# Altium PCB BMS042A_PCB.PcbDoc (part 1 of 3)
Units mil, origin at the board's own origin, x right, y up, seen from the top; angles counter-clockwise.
Board outline 4409.45 x 3307 mil, 6 copper layers (Top Layer, Layer 2 - PGND, Layer 3, Layer 4, Layer 5 - PGND, Bottom Layer), stack 60.8 mil thick; 273 components, 77 nets, 544 pads, 927 vias.
Unrouted connection lines stored in the file: 219.
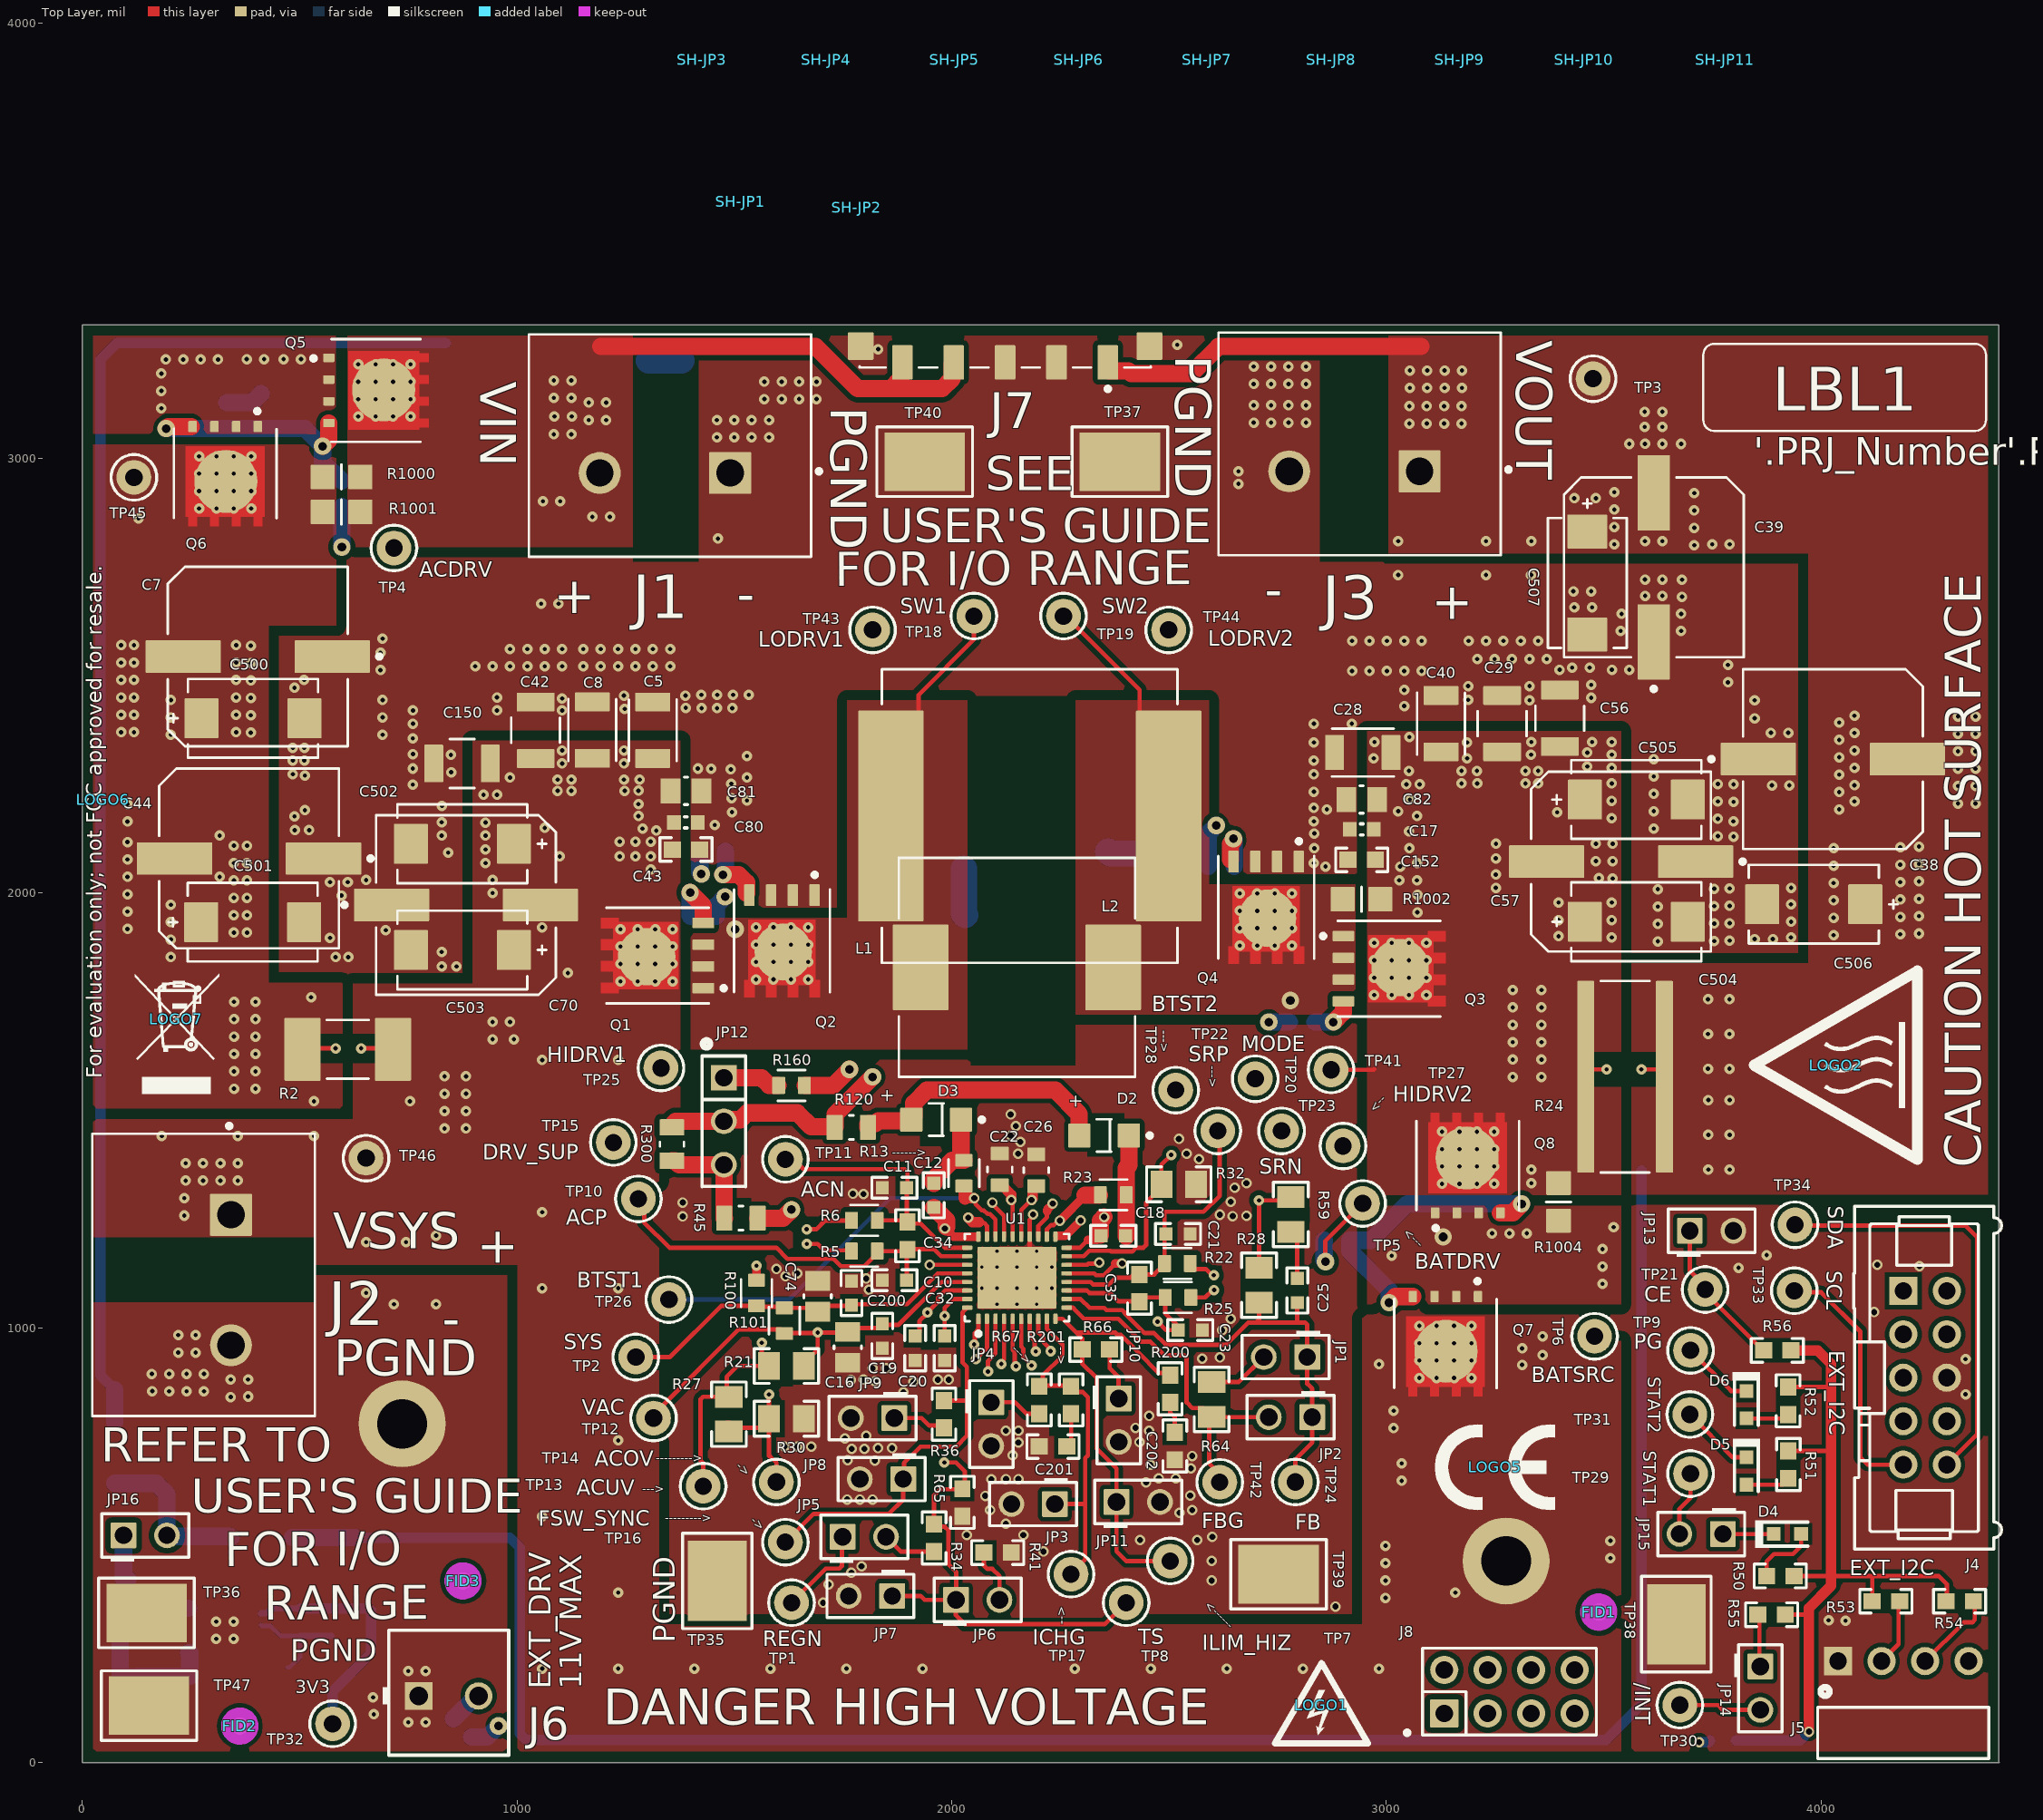
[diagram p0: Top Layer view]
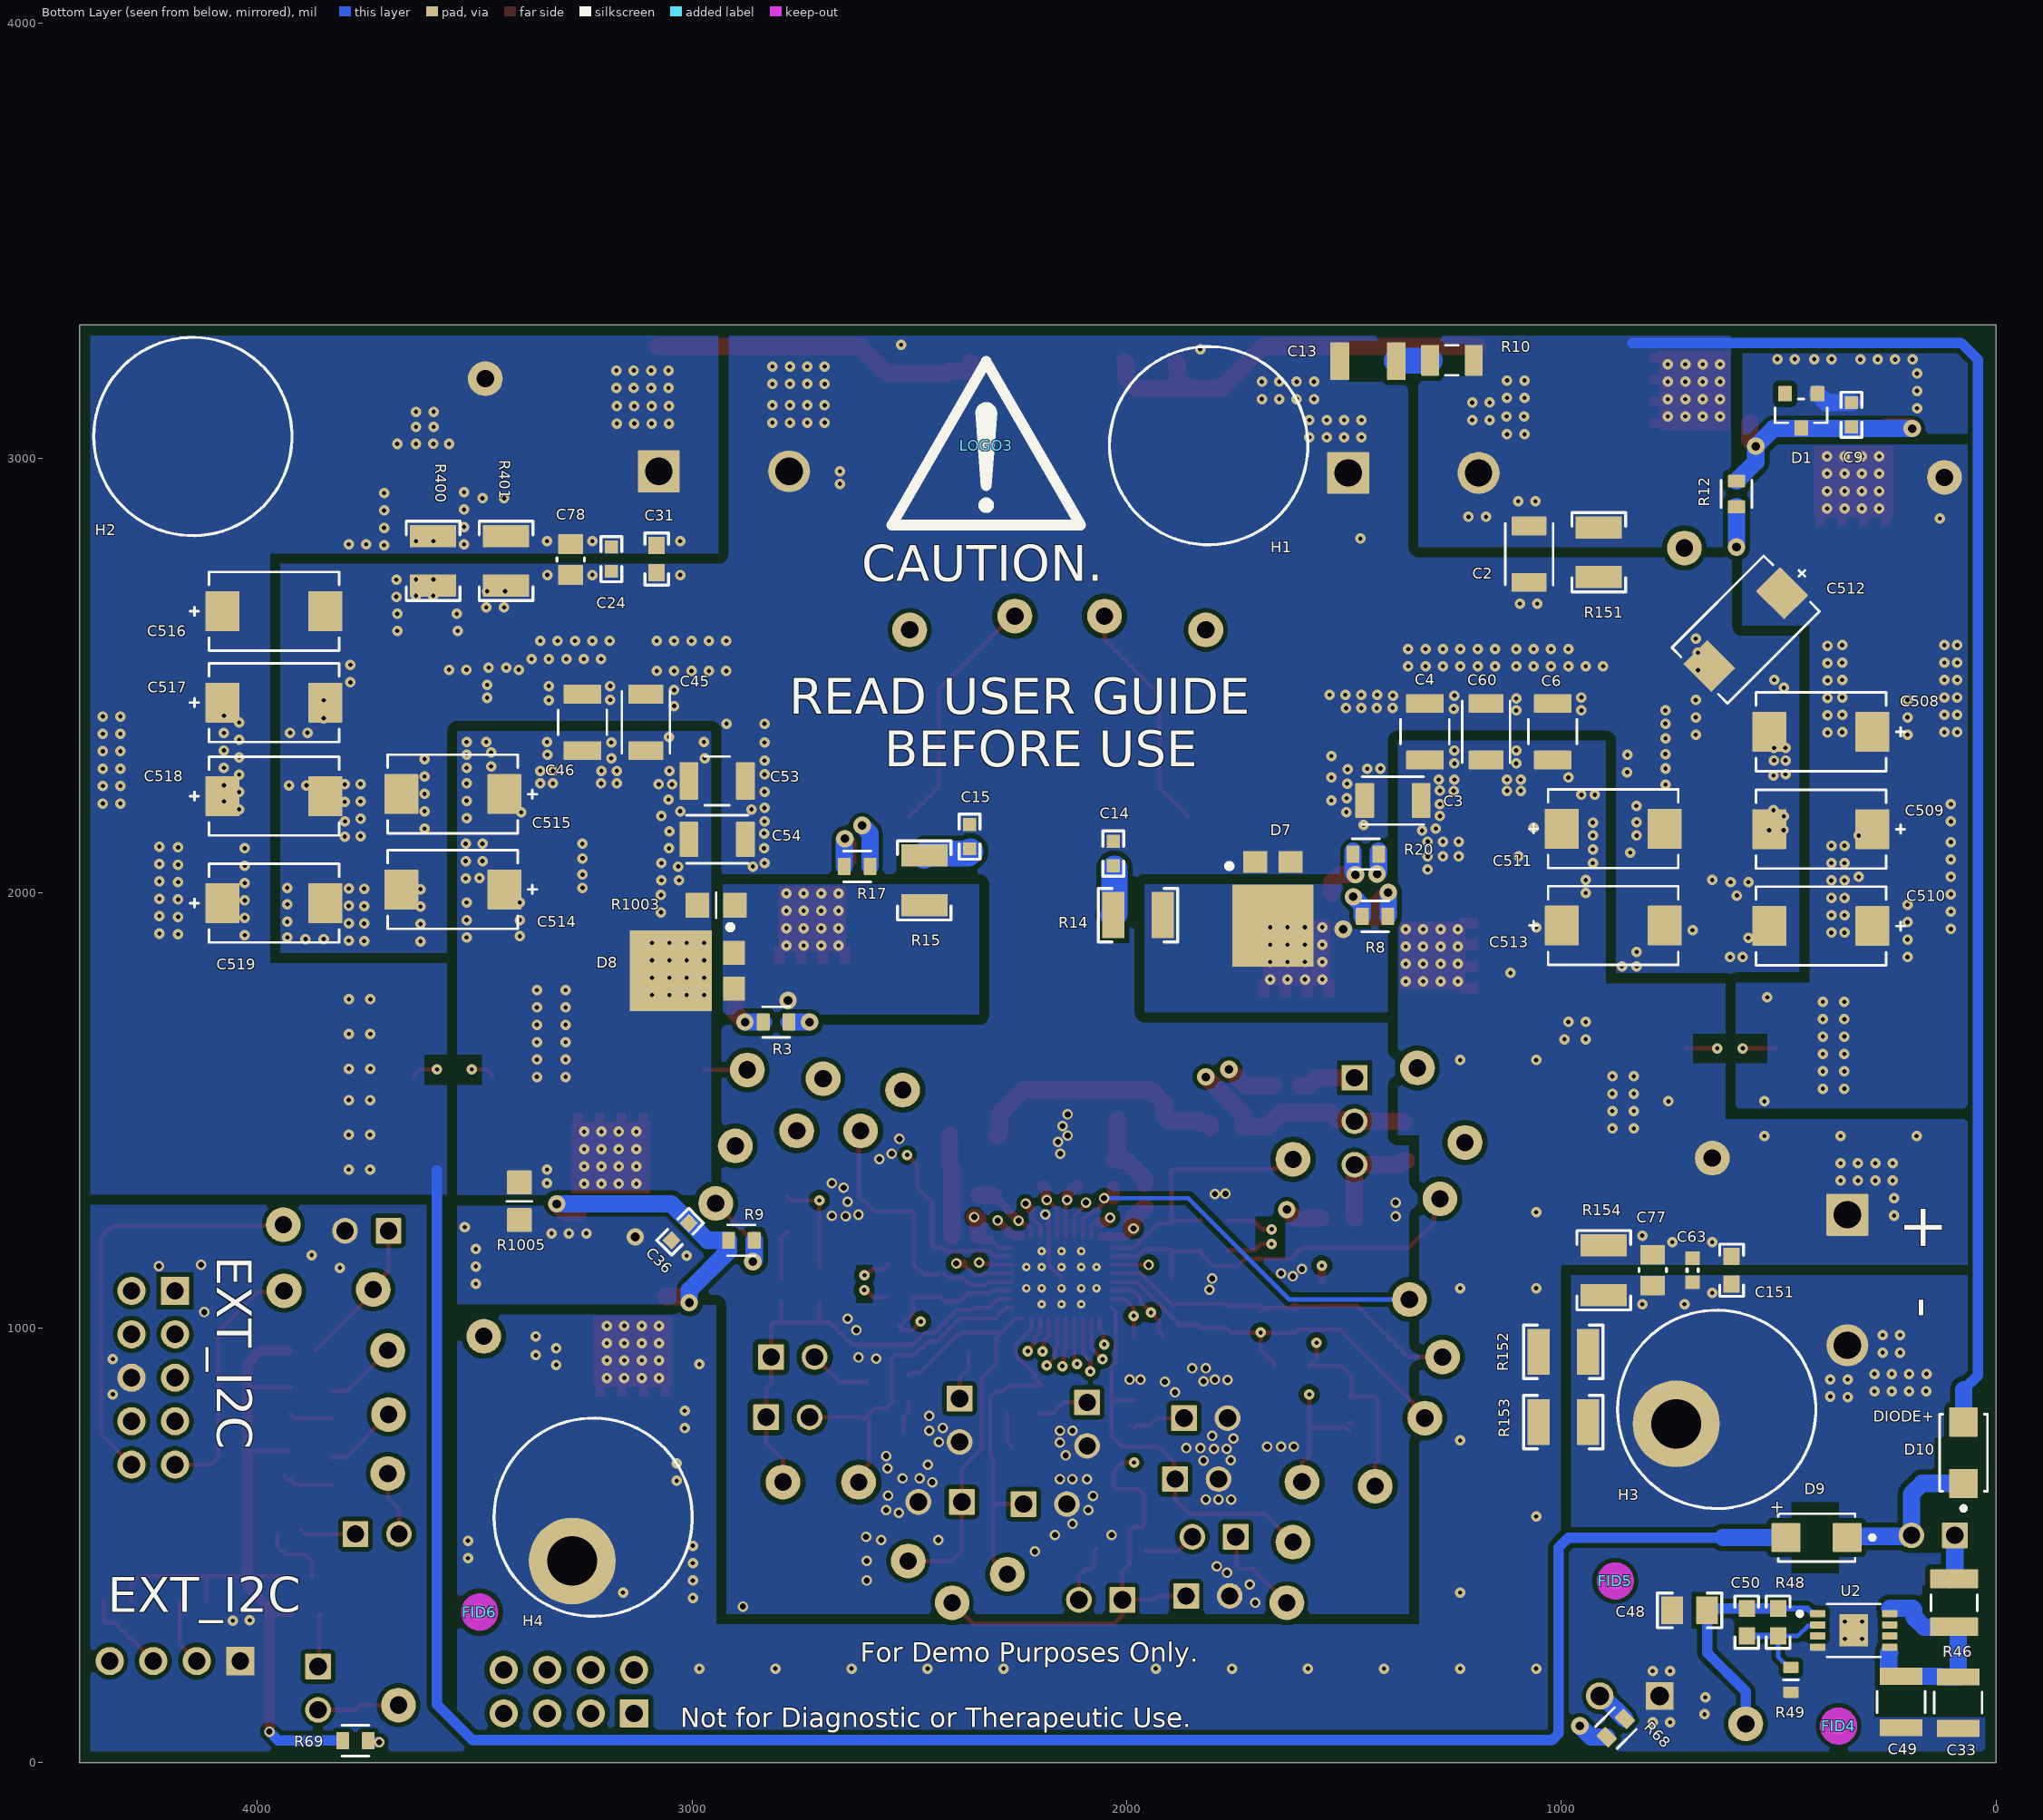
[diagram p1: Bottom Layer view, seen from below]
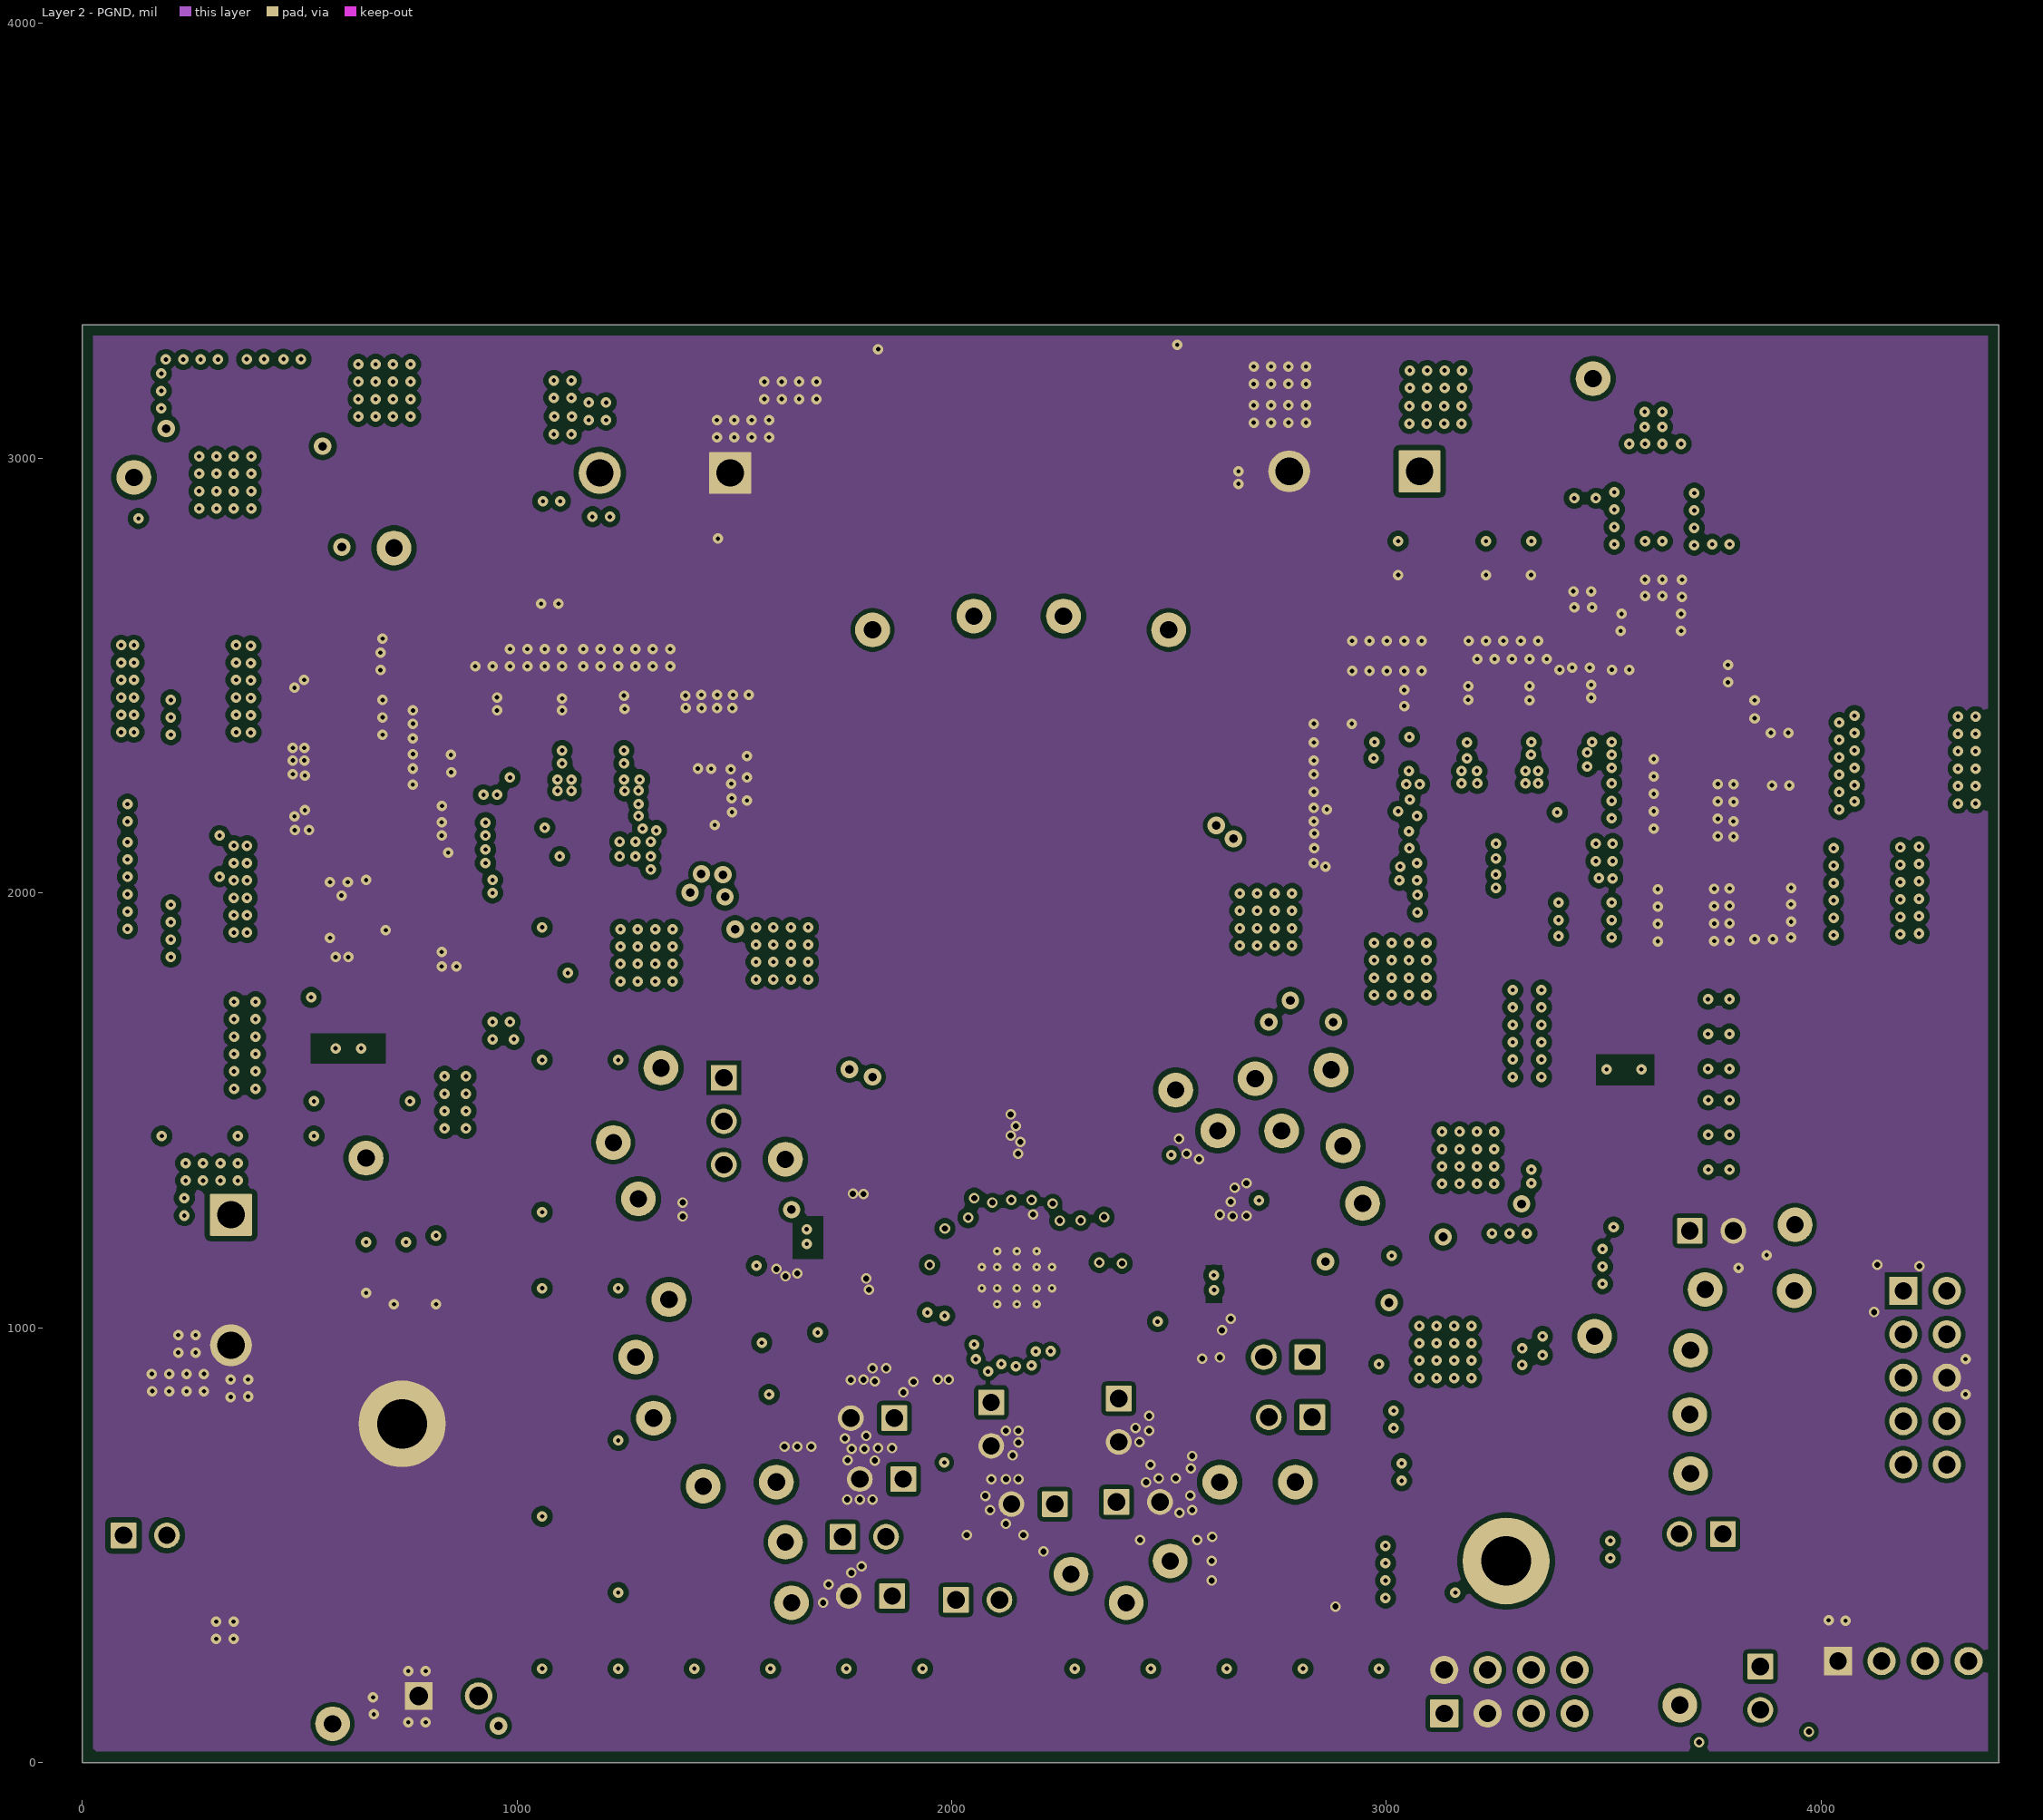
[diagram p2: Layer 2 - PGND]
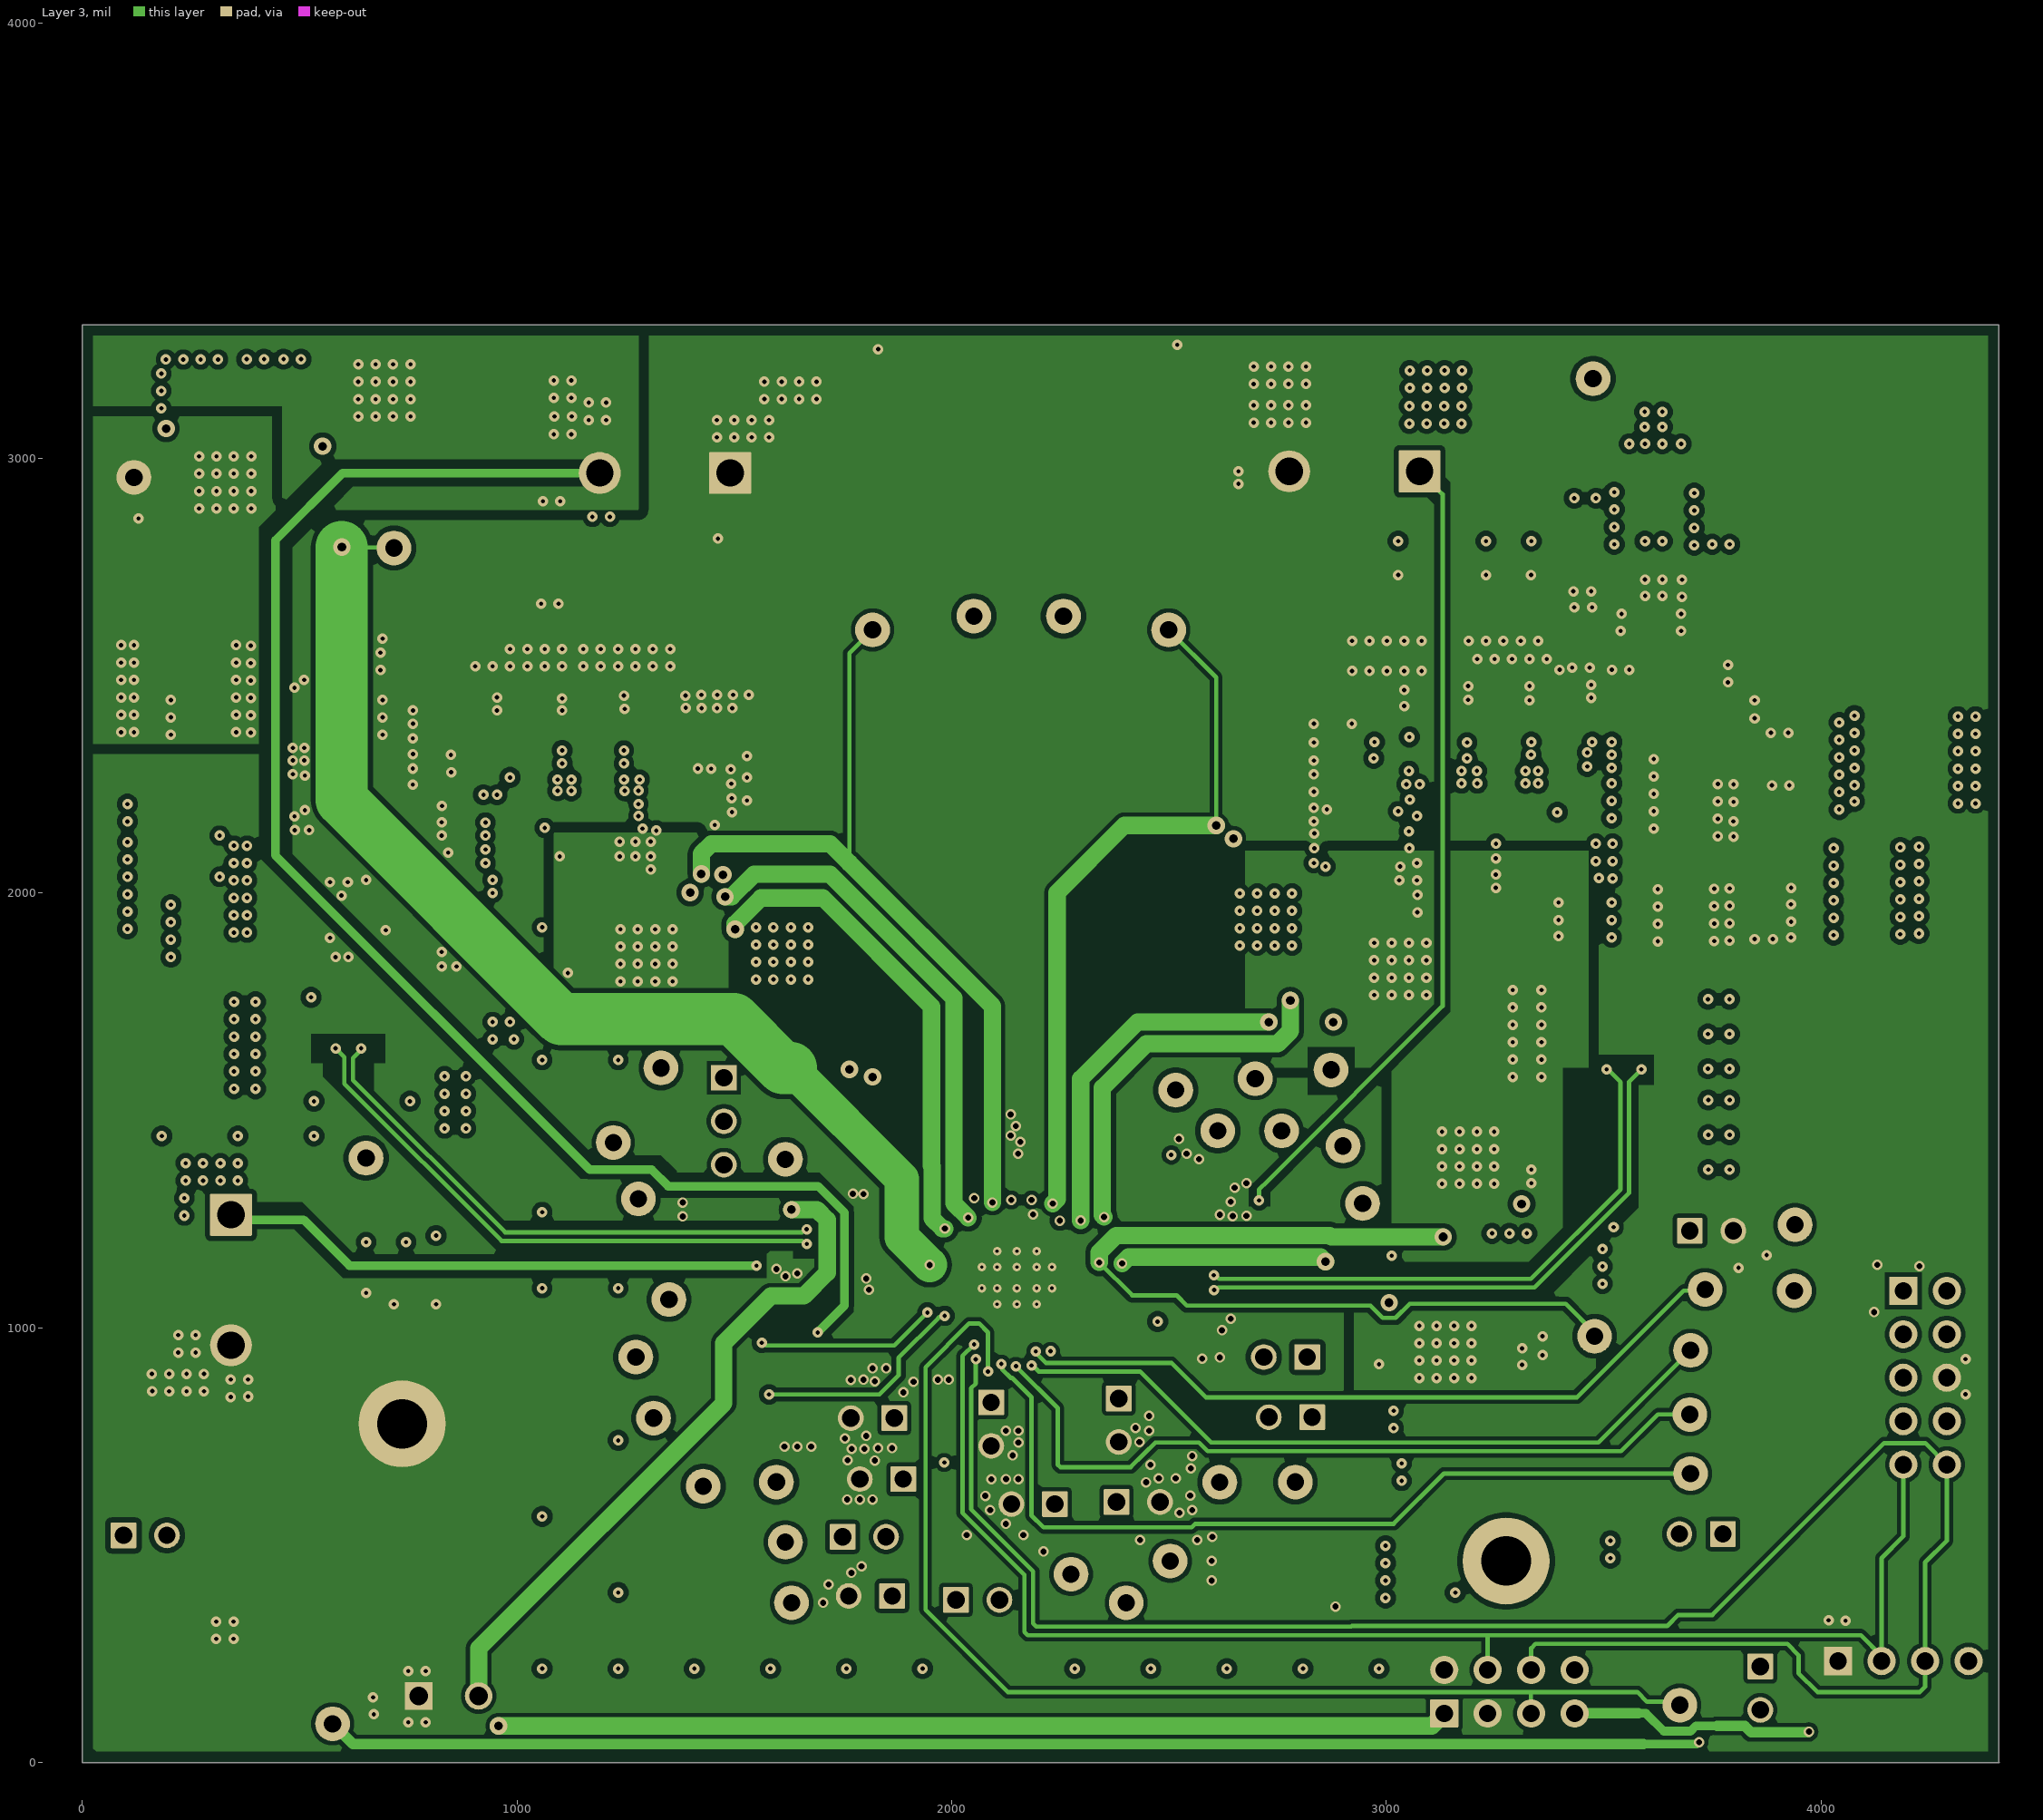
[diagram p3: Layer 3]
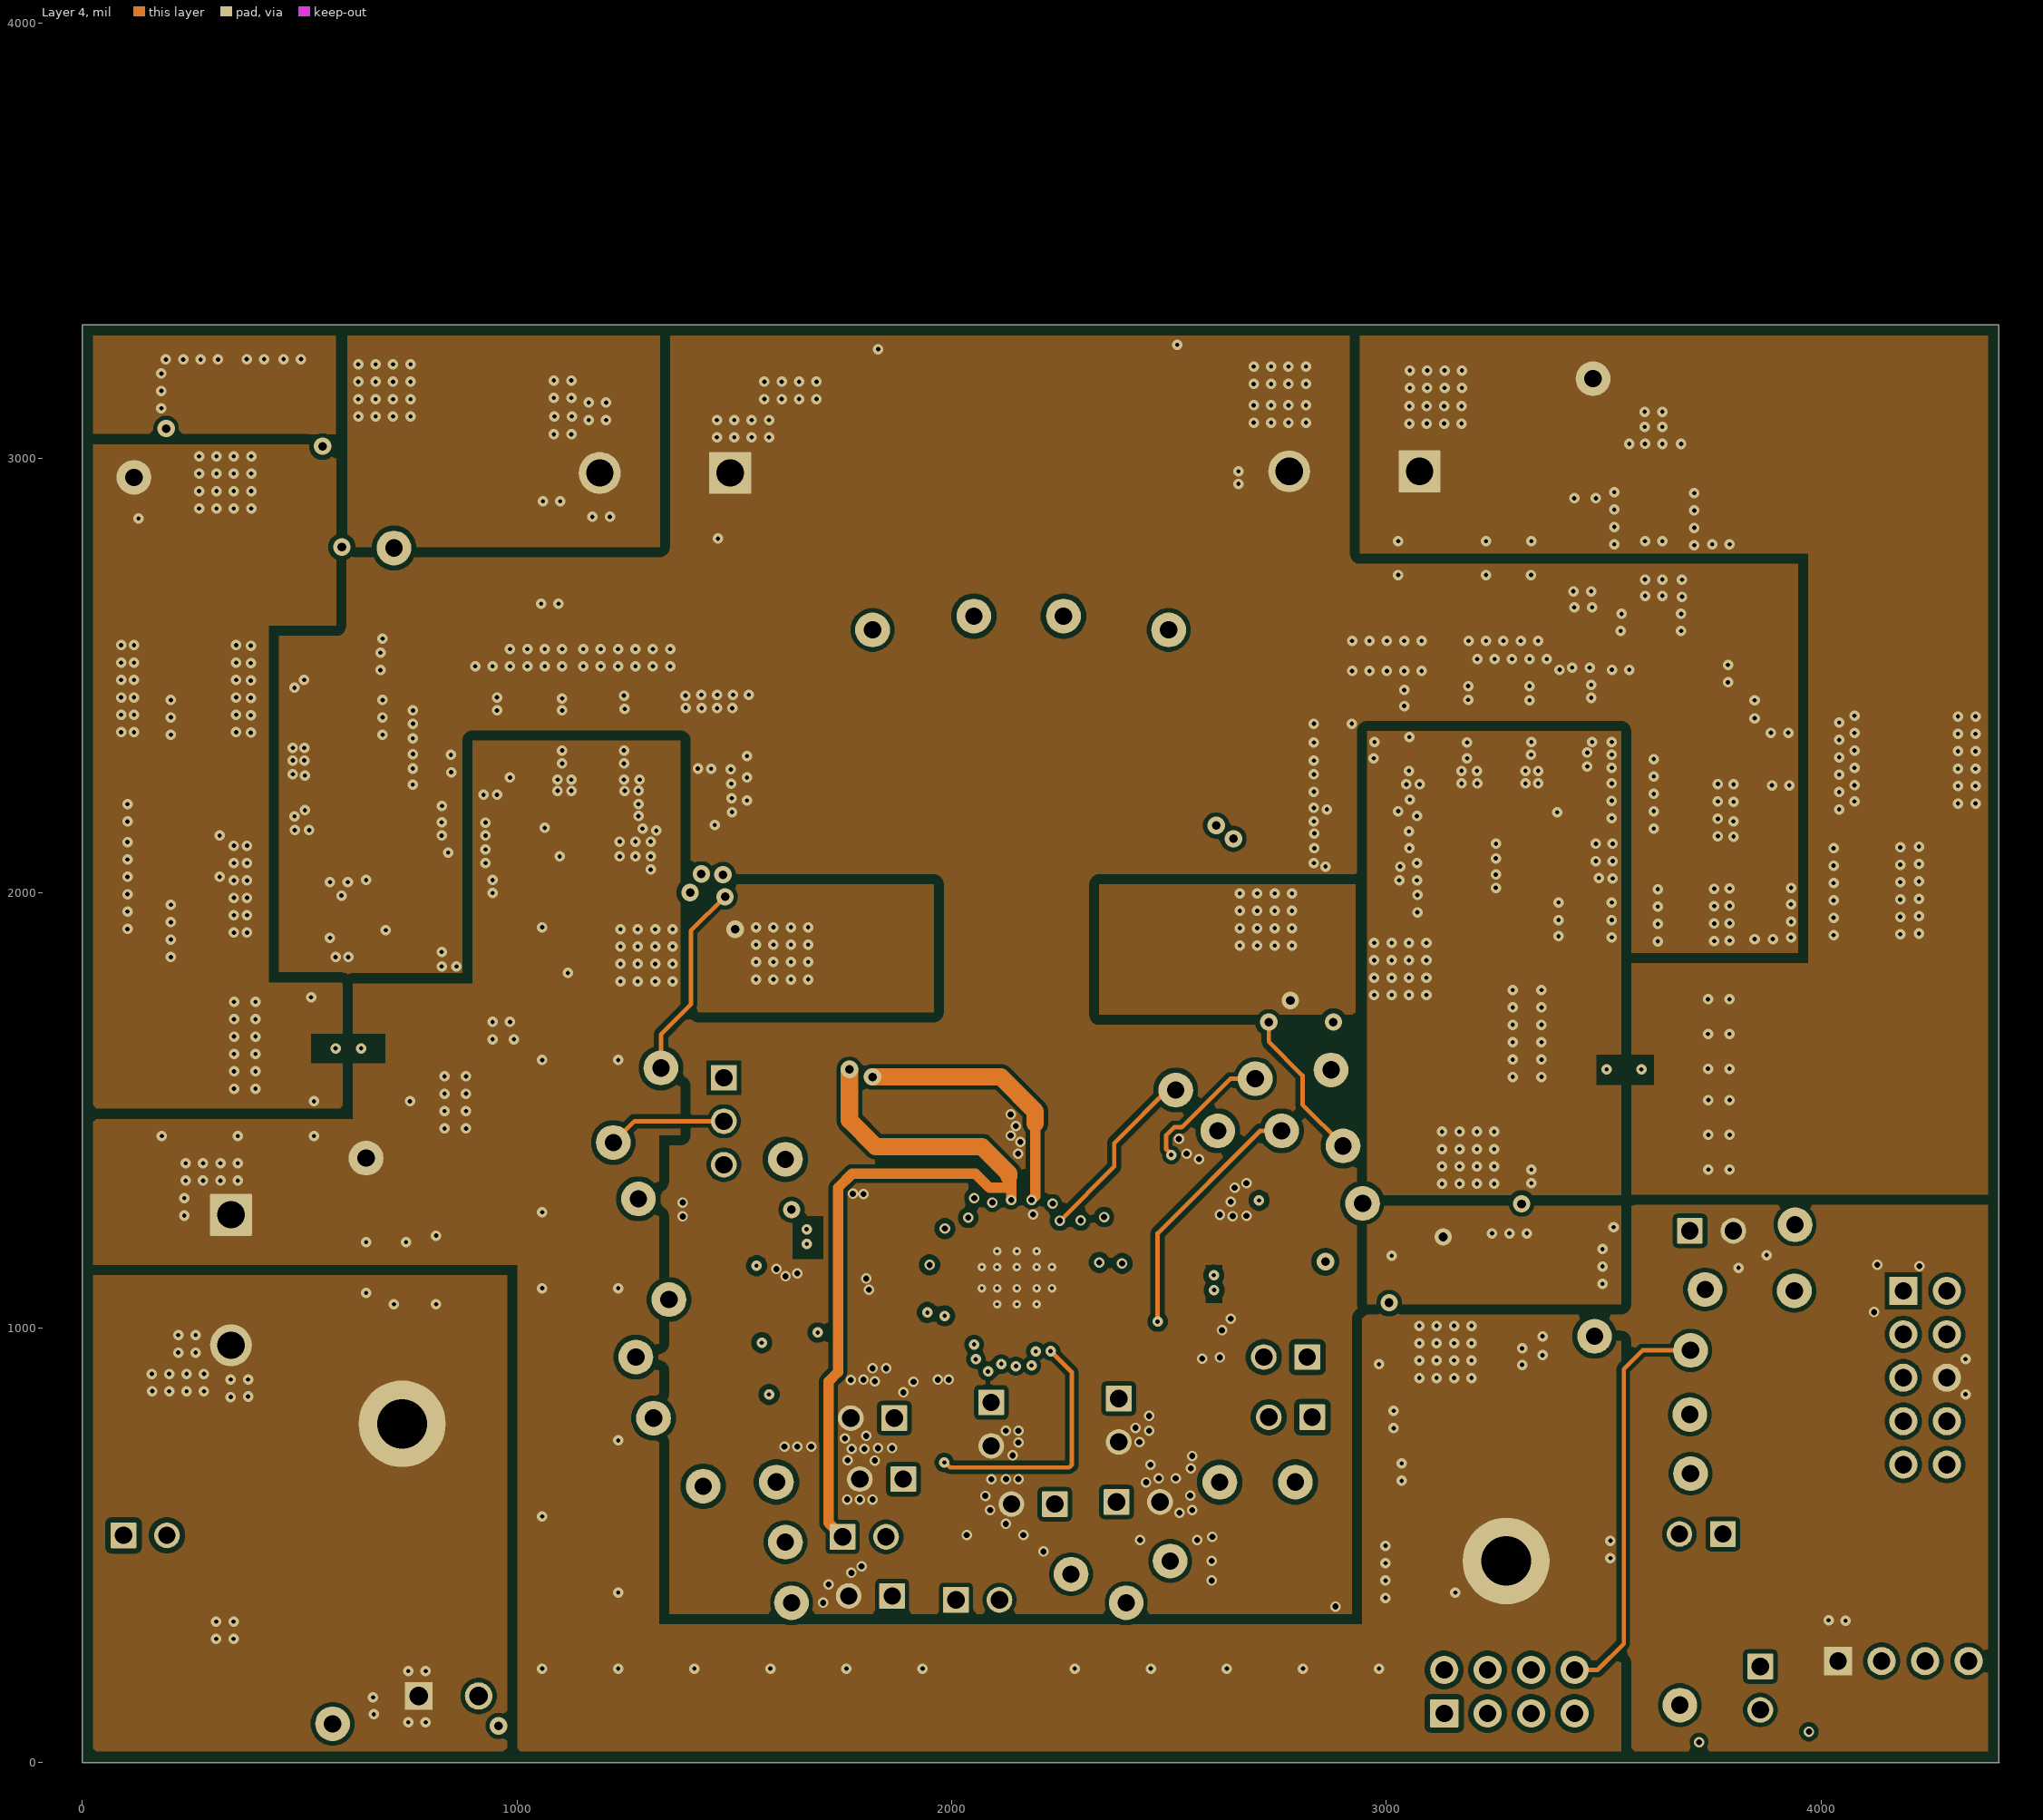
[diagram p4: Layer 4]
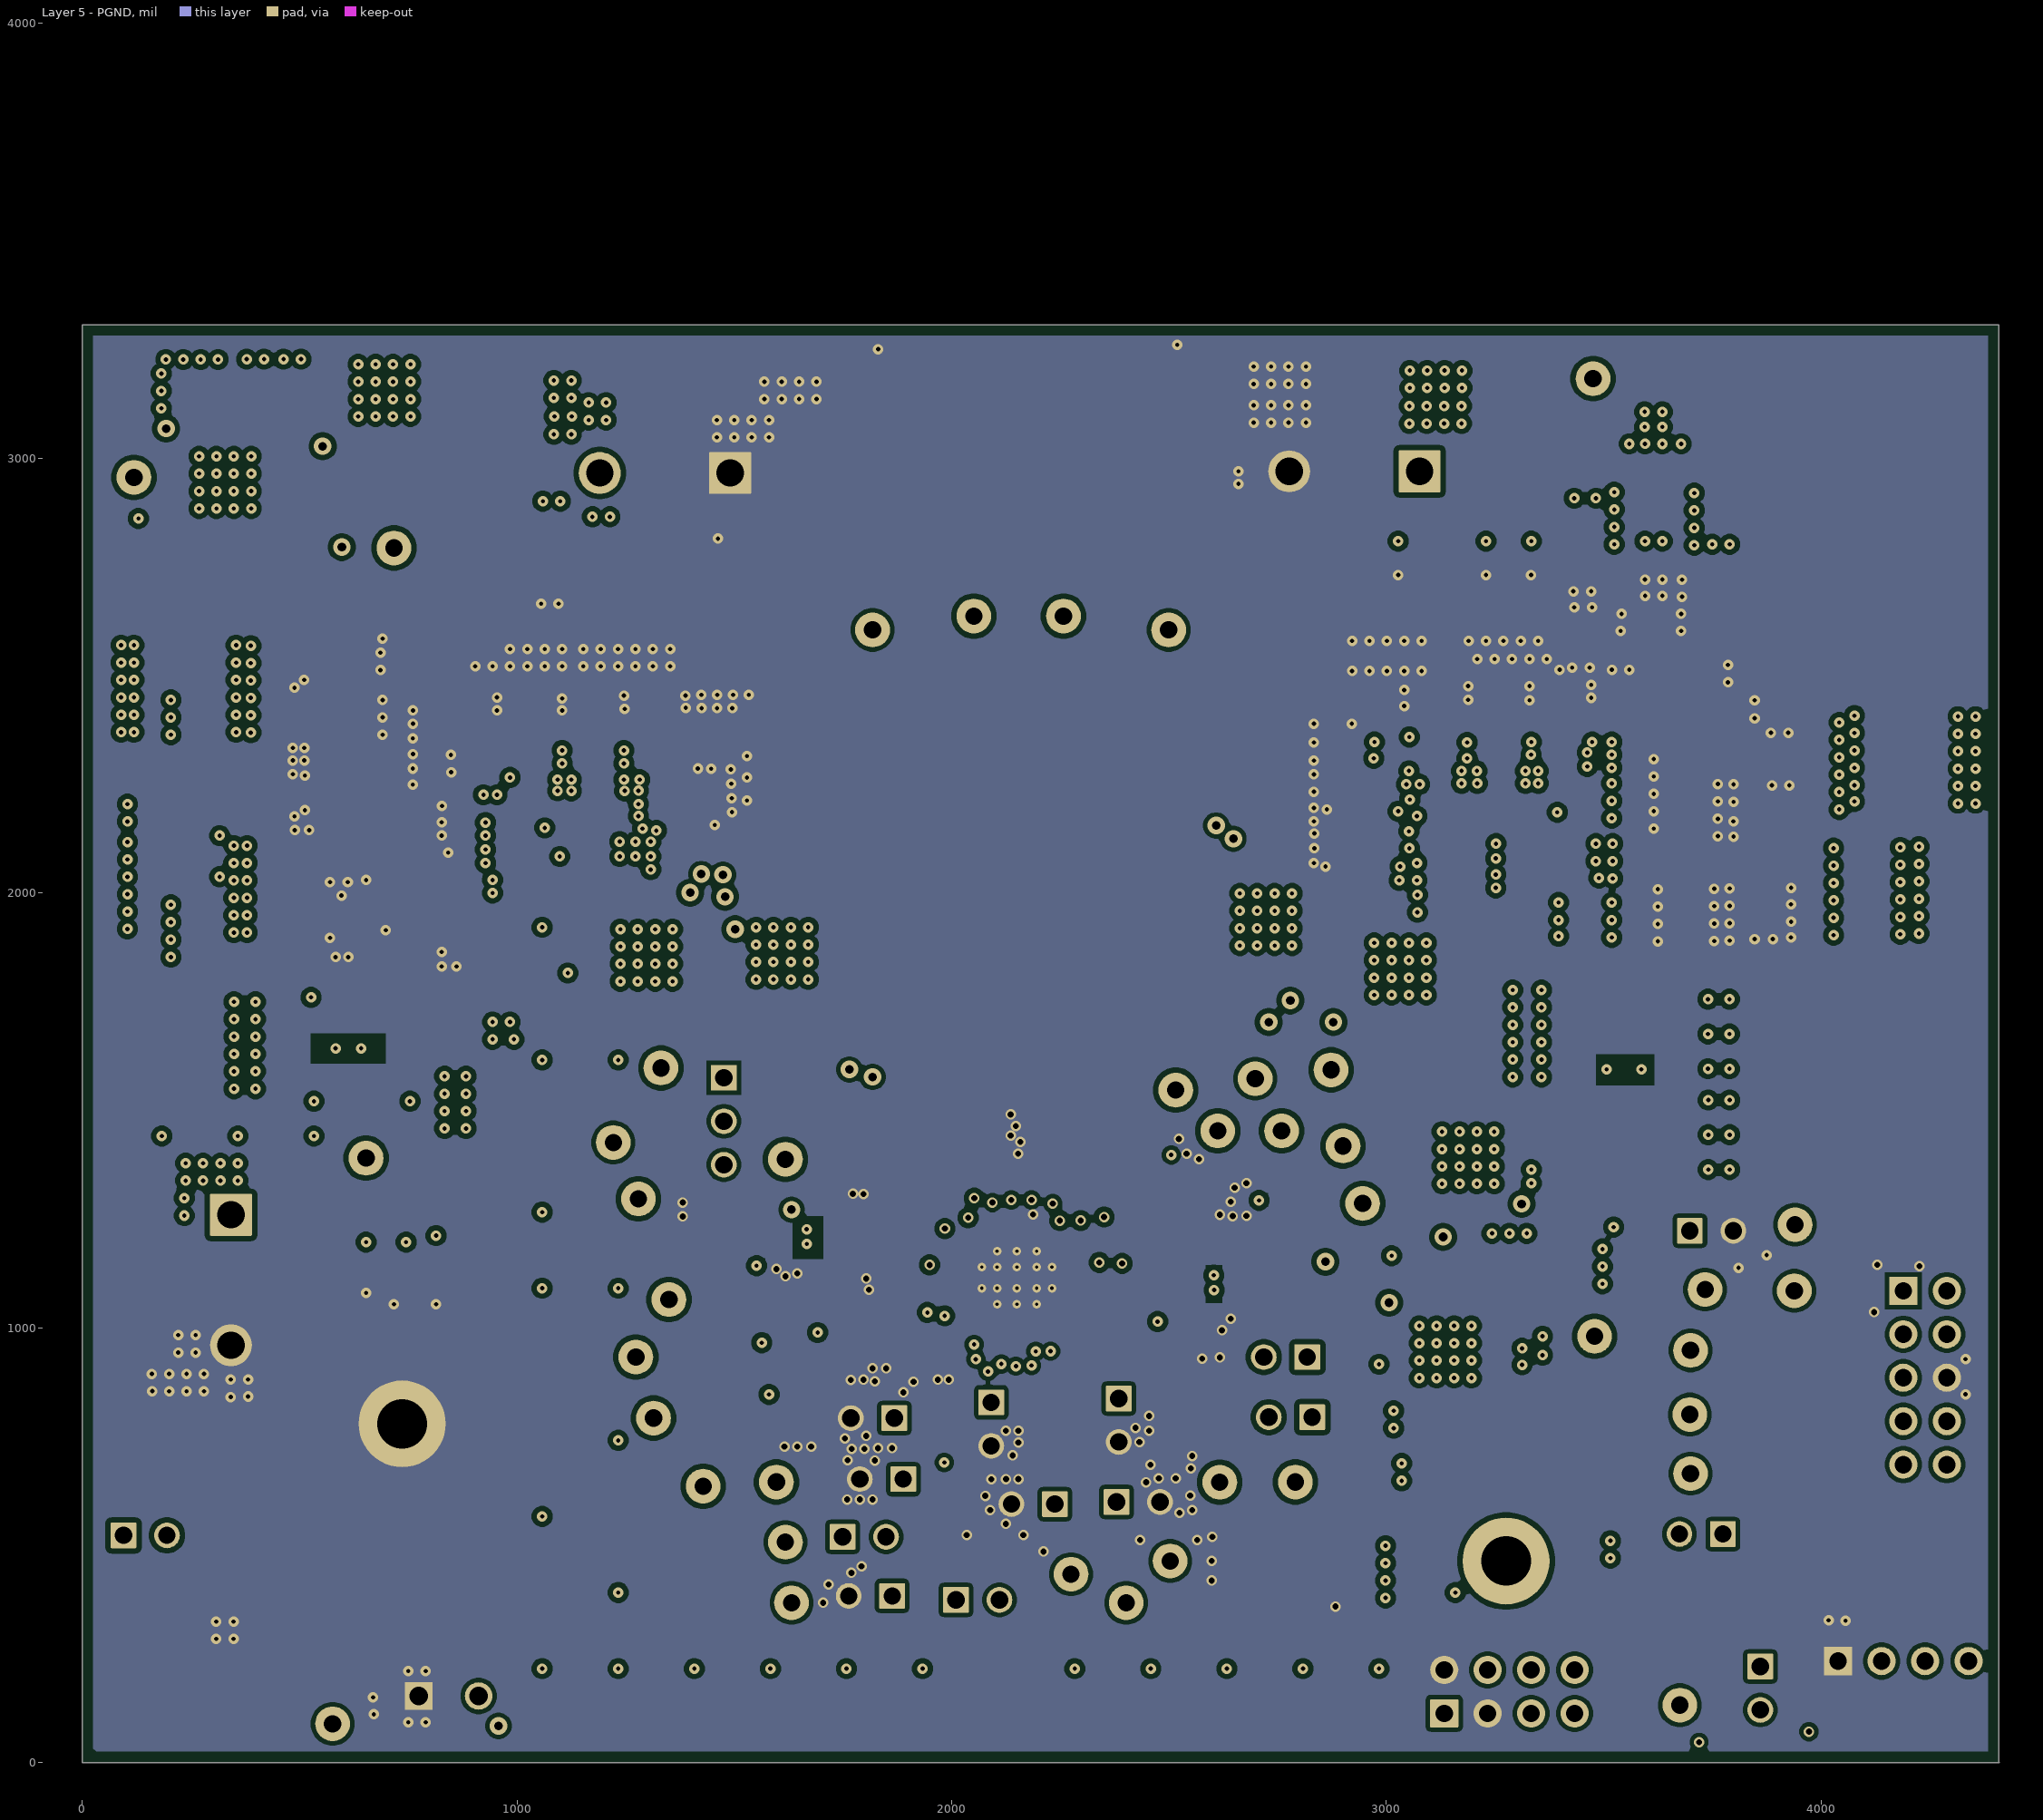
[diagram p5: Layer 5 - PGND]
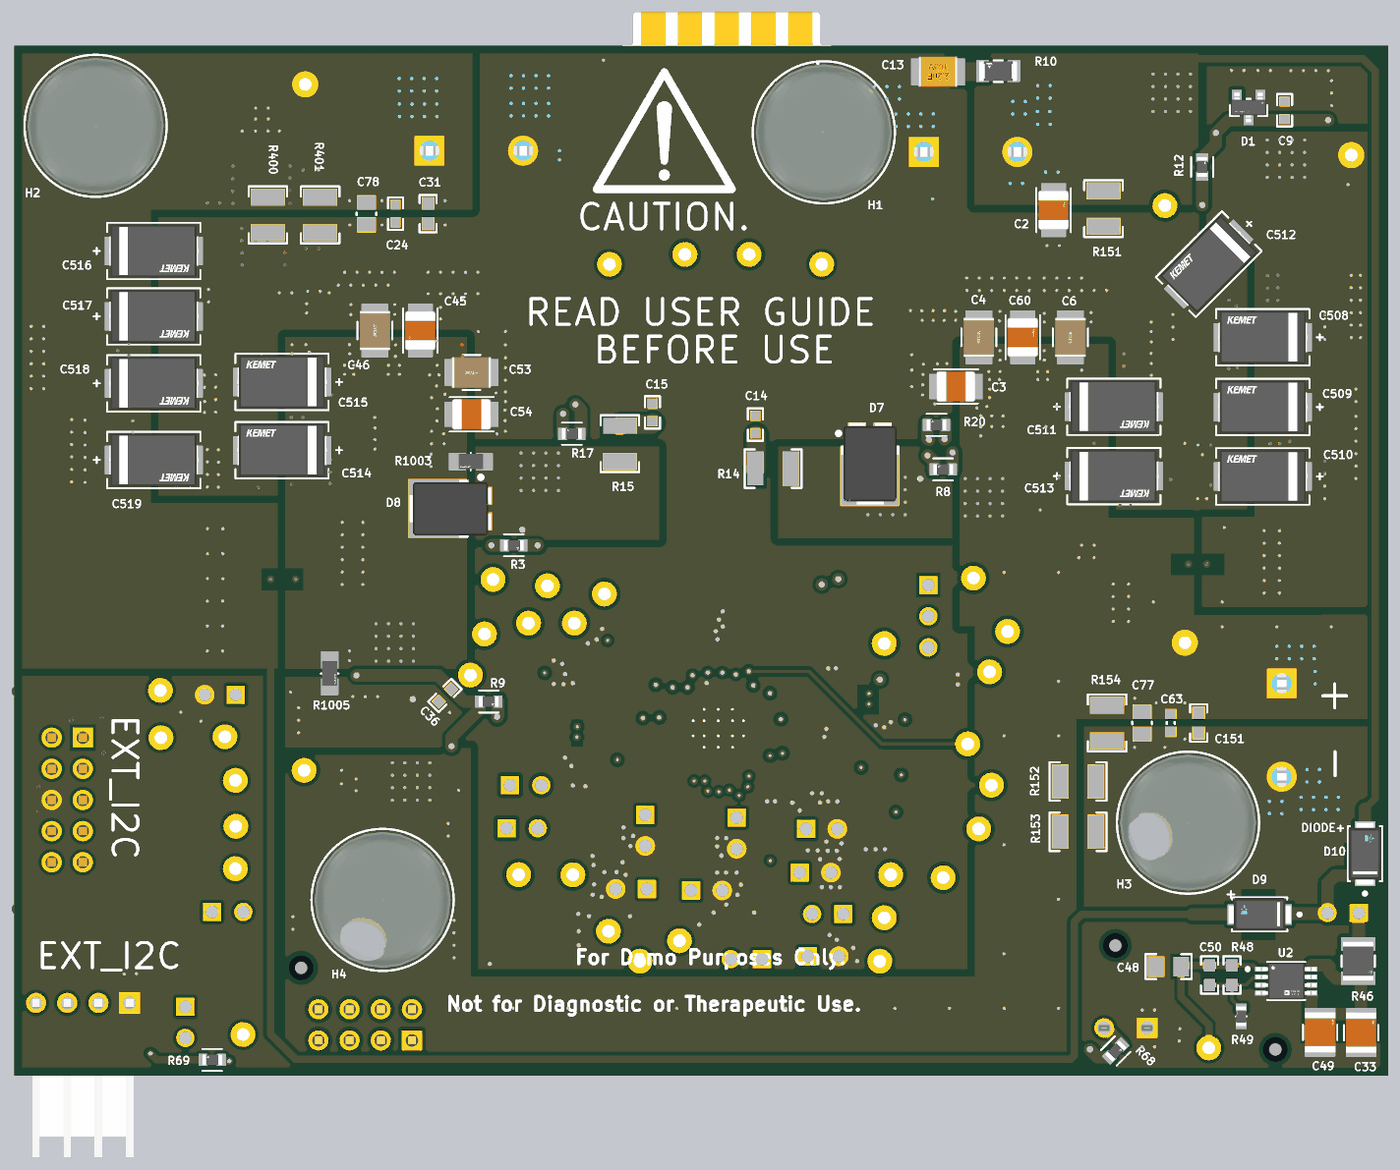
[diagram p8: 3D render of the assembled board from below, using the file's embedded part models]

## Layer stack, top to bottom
Top Solder: solder mask 0.6, Solder Resist, Dk 3.5
Top Layer: signal copper 2.8
Dielectric 1: prepreg 9, FR-4 High-Tg, Dk 4.2
Layer 2 - PGND: signal copper 2.8
Dielectric 2: core 10, FR-4 High-Tg, Dk 4.2
Layer 3: signal copper 2.8
Dielectric 4: prepreg 6, FR-4 High-Tg, Dk 4.2
Layer 4: signal copper 2.8
Dielectric 5: core 10, FR-4 High-Tg, Dk 4.2
Layer 5 - PGND: signal copper 2.8
Dielectric 3: prepreg 9, FR-4 High-Tg, Dk 4.2
Bottom Layer: signal copper 2.8
Bottom Solder: solder mask 0.6, Solder Resist, Dk 3.5

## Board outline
0,0 4409.45,0 4409,0.45 4409,3307 0,3307

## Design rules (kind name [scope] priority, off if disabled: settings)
AcuteAngle [All] p1: minimum=4.50000000000000E+0001 checktracksonly=FALSE
AssemblyTestPointUsage [All] p1: valid=2
BoardOutlineClearance BoardOutlineClearance_MountingHoles [OnCopper and InComponentClass('Mounting Holes')] p1: gap=10 ignorepadtopadclearanceinfootprint=FALSE
BoardOutlineClearance BoardOutlineClearance_Poly [OnCopper and IsPoly] p2: gap=25 ignorepadtopadclearanceinfootprint=FALSE
BoardOutlineClearance [OnCopper and Not InComponentClass('Logo') and not InComponentClass('FiducialMark') and not InRegion(1000,500,4000,800) and not InPoly] p3: gap=30 ignorepadtopadclearanceinfootprint=FALSE
Clearance Clearance_HV [InNetClass('HV') AND Inpolygon vs InPolygon] p1: gap=23.62 ignorepadtopadclearanceinfootprint=TRUE
Clearance Clearance_HV_GND [InNetClass('HV') vs InNet('PGND') OR InNet('AGND')] p2: gap=11.81 ignorepadtopadclearanceinfootprint=TRUE
Clearance Clearance_ACDRV [InNet('ACDRV') OR InNet('NetC9_2') vs InNet('NetC9_1')] p3: gap=9.84 ignorepadtopadclearanceinfootprint=TRUE
Clearance Clearance_BATDRV [InNet('BAT_DRV') OR InNet('NetC36_1') vs InNet('BAT_SRC')] p4: gap=9.84 ignorepadtopadclearanceinfootprint=TRUE
Clearance Clearance_LODRV1 [InNet('LODRV1') OR InNet('NetQ8_4') OR InNet('NetQ7_4') vs InNet('PGND') OR InNet('AGND')] p5: gap=9.84 ignorepadtopadclearanceinfootprint=TRUE
Clearance Clearance_HIDRV1 [InNet('HIDRV1') OR InNet('NetQ3_4') OR InNet('NetQ4_4') vs InNet('SW1')] p6: gap=9.84 ignorepadtopadclearanceinfootprint=TRUE
Clearance Clearance_LODRV2 [InNet('LODRV2') OR InNet('NetQ10_4') OR InNet('NetQ9_4') vs InNet('PGND') OR InNet('AGND')] p7: gap=9.84 ignorepadtopadclearanceinfootprint=TRUE
Clearance Clearance_HIDRV2 [InNet('HIDRV2') OR InNet('NetQ6_4') OR InNet('NetQ5_4') vs InNet('SW2')] p8: gap=9.84 ignorepadtopadclearanceinfootprint=TRUE
Clearance Clearance_HV_Trace_Polygon [All vs InNetClass('HV') AND Inpolygon] p9: gap=11.81 ignorepadtopadclearanceinfootprint=TRUE
Clearance Clearance_HV_NC [InNetClass('All Nets') vs InNet('NC')] p10: gap=23.62 ignorepadtopadclearanceinfootprint=TRUE
Clearance [All] p11: gap=9.84 ignorepadtopadclearanceinfootprint=TRUE
Clearance Clearance_Poly [InPolygon] p12: gap=9.84 ignorepadtopadclearanceinfootprint=TRUE
Clearance Clearance_Keepouts [((IsTrack Or IsArc) And Not InPoly) And IsFree and IsKeepOut vs ((IsTrack Or IsArc) And Not InPoly) And IsFree and IsKeepOut] p13: gap=9.84 ignorepadtopadclearanceinfootprint=FALSE
Clearance Clearance_FiducialMark [IsKeepOut and InComponentClass('FiducialMark') vs IsPad and InComponentClass('FiducialMark')] p14: gap=9.84 ignorepadtopadclearanceinfootprint=FALSE
ComponentClearance ComponentClearance_MountingHoles_FiducialMarks [InComponentClass('Mounting Holes') vs InComponentClass('FiducialMark')] p1: gap=50 collisioncheckmode=3 verticalgap=7.87 showdistances=FALSE
ComponentClearance ComponentClearance_Shunt [InComponentClass('Header') vs InComponentClass('Shunt')] p2: gap=7.87 collisioncheckmode=3 verticalgap=7.87 showdistances=FALSE
ComponentClearance ComponentClearance_Logo [InComponentClass('Logo')] p3: gap=50 collisioncheckmode=3 verticalgap=7.87 showdistances=FALSE
ComponentClearance ComponentClearance_ScrewToNut [(HasFootprint('NY PMS 440 0025 PH')) vs (HasFootprint('Keystone_1902C'))] p4: gap=5 collisioncheckmode=3 verticalgap=7.87 showdistances=FALSE
ComponentClearance ComponentClearance_MountingHoles [InComponentClass('Mounting Holes')] p5: gap=250 collisioncheckmode=3 verticalgap=100000 showdistances=FALSE
ComponentClearance ComponentClearance_SmallPassives [HasFootprint('0201*') or HasFootprint('0402*') or HasFootprint('0508') or HasFootprint('0603*') or HasFootprint('0612') or HasFootprint('0805*') or HasFootprint('0815*') or HasFootprint('0830*') or HasFootprint('1206*') or HasFootprint('1210*') or HasFootprint('1808*') or HasFootprint('1812*') or HasFootprint('1825*') or HasFootprint('2010*') or HasFootprint('2220*') or HasFootprint('2225*') or HasFootprint('2512*') or HasFootprint('2728*') or HasFootprint('3518*') vs HasFootprint('0201*') or HasFootprint('0402*') or HasFootprint('0508') or HasFootprint('0603*') or HasFootprint('0612') or HasFootprint('0805*') or HasFootprint('0815*') or HasFootprint('0830*') or HasFootprint('1206*') or HasFootprint('1210*') or HasFootprint('1808*') or HasFootprint('1812*') or HasFootprint('1825*') or HasFootprint('2010*') or HasFootprint('2220*') or HasFootprint('2225*') or HasFootprint('2512*') or HasFootprint('2728*') or HasFootprint('3518*')] p6: gap=7.87 collisioncheckmode=3 verticalgap=7.87 showdistances=FALSE
ComponentClearance ComponentClearance_THtoSMT [IsThruComponent vs IsSMTComponent] p7: gap=40 collisioncheckmode=3 verticalgap=30 showdistances=FALSE
ComponentClearance ComponentClearance_THtoTH [IsThruComponent vs IsThruComponent] p8: gap=30 collisioncheckmode=3 verticalgap=30 showdistances=FALSE
ComponentClearance ComponentClearance_Inductor [InComponent('L1') vs InComponent('L2')] p9: gap=0 collisioncheckmode=3 verticalgap=0 showdistances=FALSE
ComponentClearance ComponentClearance_buck_only_resistor [InComponent('R68') vs InComponent('Q5') OR InComponent('Q6')] p10: gap=10 collisioncheckmode=3 verticalgap=7.87 showdistances=FALSE
ComponentClearance [All] p11: gap=30 collisioncheckmode=3 verticalgap=7.87 showdistances=FALSE
DiffPairsRouting [All] p1: maxlimit=100 minlimit=10 mostfreqgap=10 toplayer_minwidth=15 toplayer_maxwidth=15 toplayer_prefwidth=15 midlayer1_minwidth=15 midlayer1_maxwidth=15 midlayer1_prefwidth=15 midlayer2_minwidth=15 midlayer2_maxwidth=15 midlayer2_prefwidth=15 midlayer3_minwidth=15 midlayer3_maxwidth=15 midlayer3_prefwidth=15 midlayer4_minwidth=15 midlayer4_maxwidth=15 midlayer4_prefwidth=15 bottomlayer_minwidth=15 bottomlayer_maxwidth=15 bottomlayer_prefwidth=15 maxuncoupledlength=1000
FabricationTestPointUsage TestPointUsage [All] p1: valid=2 allowmultiple=FALSE
FabricationTestpoint Testpoint [All] p1: side=3 testpointundercomponent=TRUE minsize=40 maxsize=100 preferedsize=60 minholesize=0 maxholesize=40 preferedholesize=32 testpointgrid=1 allowsidetop=TRUE allowsidebottom=TRUE usegrid=TRUE gridtolerance=0.01
FanoutControl Fanout_LCC [IsLCC] p1: bgadir=Out bgaviamode=Centered fanoutstyle=Auto fanoutdirection=Alternating viagrid=1 // Fanout_LCC (Default Rule)
FanoutControl Fanout_BGA [IsBGA] p2: bgadir=Out bgaviamode=Centered fanoutstyle=Auto fanoutdirection=Alternating viagrid=1 // Fanout_BGA (Default Rule)
FanoutControl Fanout_Default [All] p4: bgadir=Out bgaviamode=Centered fanoutstyle=Auto fanoutdirection=Alternating viagrid=1 // Fanout_Default (Default Rule)
FanoutControl Fanout_Small [(CompPinCount < 5)] p5: bgadir=Out bgaviamode=Centered fanoutstyle=Auto fanoutdirection=OutThenIn viagrid=1 // Fanout_Small (Default Rule)
HoleSize [All] p1: absolutevalues=TRUE maxlimit=251 minlimit=7.87 maxpercent=80.000 minpercent=20.000
MinimumAnnularRing MinimumAnnularRing_ThermalPadVias [IsVia and InAnyComponent] p1: minimumring=5.91
MinimumAnnularRing [All] p2: minimumring=4.9
MinimumSolderMaskSliver MinimumSolderMaskSliver_Logo [InComponentClass('Logo') vs InComponentClass('Logo')] p1: minsoldermaskwidth=0.7
MinimumSolderMaskSliver [All] p2: minsoldermaskwidth=3.94
PlaneConnect [All] p1: planeconnectstyle=Direct reliefexpansion=10 reliefentries=4 reliefconductorwidth=10 reliefairgap=10
PolygonConnect [All] p1: connectstyle=Direct reliefconductorwidth=10 reliefentries=4 polygonreliefangle="90 Angle" airgapwidth=10
RoutingVias ThermalPadVias [IsVia and InAnyComponent] p1: holewidth=7.87 width=19.68 viastyle="Through Hole" minholewidth=7.87 minwidth=19.68 maxholewidth=12.99 maxwidth=23.62
RoutingVias [All] p2: holewidth=16 width=34 viastyle="Through Hole" minholewidth=7.87 minwidth=20 maxholewidth=40 maxwidth=65
SilkToBoardRegionClearance [Not ((IsComment or IsDesignator) And (Hide <> 'False')) and not InRegion(1000,500,4000,800)] p1:
SilkToSilkClearance SilkToSilkClearance_Pb-FreeLogo [(HasFootprint('Pb-Free_Overlay_Medium') OR HasFootprint('Pb-Free_Overlay_Small')) vs (HasFootprint('Pb-Free_Overlay_Medium') OR HasFootprint('Pb-Free_Overlay_Small'))] p1: silktosilkclearance=0
SilkToSilkClearance [All] p2: silktosilkclearance=3.94
SilkToSolderMaskClearance SilkToComponentPadClearance [(IsPad or IsFill or IsRegion) and InAnycomponent] p1: minsilkscreentomaskgap=5 clearancetoexposedcopper=TRUE
SilkToSolderMaskClearance "Silk to Solder Mask Opening" [All] p2: minsilkscreentomaskgap=3.94 clearancetoexposedcopper=FALSE
SolderMaskExpansion SolderMaskExpansion_Via [IsVia] p1: expansion=1.97 istentingtop=TRUE
SolderMaskExpansion [All] p2: expansion=1.97 istentingtop=FALSE
UnRoutedNet [All] p1: checkbadconnections=TRUE
Width [All] p1: maxlimit=150 minlimit=9.84 preferedwidth=20 checkconnectedcopper=TRUE
14 further rules are at their usual default settings.

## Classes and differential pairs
component class powerpath_capacitors: C3 C4 C5 C6 C7 C8 C17 C24 C28 C29 C31 C38 C39 C40 C42 C43 C44 C45 C46 C53 C54 C56 C57 C60 C70 C78 C80 C81 C82 C150 C152 C500 C501 C502 C503 C504 C505 C506 C507 C508 C509 C510 C511 C512 C513 C514 C515 C516 C517 C518 C519 R152 R153 R154 R400 R401
component class FiducialMark: FID1 FID2 FID3 FID4 FID5 FID6
component class Shunt: SH-JP1 SH-JP2 SH-JP3 SH-JP4 SH-JP5 SH-JP6 SH-JP7 SH-JP8 SH-JP9 SH-JP10 SH-JP11
component class Label: LBL1
component class Header: J8 JP1 JP2 JP3 JP4 JP5 JP6 JP7 JP8 JP9 JP10 JP11 JP12 JP13 JP14 JP15 JP16
component class AssemblyNote: ZZ1 ZZ2 ZZ3 ZZ4 ZZ5 ZZ6 ZZ7
component class BMS042-E4_page2: C33 C48 C49 C50 C201 C202 D4 D5 D6 D9 D10 J4 J5 J6 J7 J8 JP3 JP4 JP5 JP6 JP7 JP8 JP9 JP10 JP11 JP12 JP13 JP14 JP15 JP16 R34 R36 R41 R45 R46 R48 R49 R50 R51 R52 R53 R54 R55 R56 R65 R66 R67 R68 R69 R160 R200 R201 R300 TP1 TP2 TP3 TP4 TP5 TP6 TP7 TP8 TP9 TP10 TP11 TP12 TP13 TP14 TP15 TP16 TP17 TP18 TP19 TP20 TP21 TP22 TP23 TP24 TP25 TP26 TP27 TP28 TP29 TP30 TP31 TP32 TP33 TP34 TP35 TP36 TP37 TP38 TP39 TP40 TP42 TP43 TP44 TP47 U2
component class BMS042-E4_page1: C2 C9 C10 C11 C12 C13 C14 C15 C16 C18 C19 C20 C21 C22 C23 C25 C26 C32 C34 C35 C36 C63 C74 C77 C151 C200 D1 D2 D3 D7 D8 J1 J2 J3 JP1 JP2 L1 L2 Q1 Q2 Q3 Q4 Q5 Q6 Q7 Q8 R2 R3 R5 R6 R8 R9 R10 R12 R13 R14 R15 R17 R20 R21 R22 R23 R24 R25 R27 R28 R30 R32 R59 R64 R100 R101 R120 R151 R1000 R1001 R1002 R1003 R1004 R1005 TP41 TP45 TP46 U1
component class BMS042-E4_Hardware: FID1 FID2 FID3 FID4 FID5 FID6 H1 H2 H3 H4 LBL1 LOGO1 LOGO2 LOGO3 LOGO5 LOGO6 LOGO7 PCB1 SH-JP1 SH-JP2 SH-JP3 SH-JP4 SH-JP5 SH-JP6 SH-JP7 SH-JP8 SH-JP9 SH-JP10 SH-JP11 ZZ1 ZZ2 ZZ3 ZZ4 ZZ5 ZZ6 ZZ7
net class HV: AC_OUT ACDRV ACN ACOV ACP ACUV BAT BAT_DRV BAT_SRC BTST1 BTST2 FB FBG HIDRV1 HIDRV2 NetC9_1 NetC9_2 NetC12_2 NetC13_1 NetC14_1 NetC15_1 NetC18_1 NetC25_1 NetC33_2 NetC36_1 NetD9_1 NetJP1_2 NetJP16_1 NetQ1_4 NetQ3_4 P_OUT SRN SRP SW1 SW2 SYS VAC VSYS

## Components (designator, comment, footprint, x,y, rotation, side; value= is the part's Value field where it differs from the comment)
C2 "GCJ32DC72A475KE01L" FP-GCJ32DC72A475KE01L_1210-MFG 1074.28,2779.32 r90 bottom value=4.7µF
C3 "GCJ32DC72A475KE01L" FP-GCJ32DC72A475KE01L_1210-MFG 1387.59,2212.75 r0 bottom value=4.7µF
C4 "C3225X7R2A106K250AC" FP-C3225X7R2A106K250AC_1210-MFG 1313.95,2370.88 r90 bottom value=10µF
C5 "GCJ32DC72A475KE01L" FP-GCJ32DC72A475KE01L_1210-MFG 1312.48,2374.29 r270 top value=4.7µF
C6 "C3225X7R2A106K250AC" FP-C3225X7R2A106K250AC_1210-MFG 1020.15,2370.88 r90 bottom value=10µF
C7 "80SXV47M" FP-100SXV22M_RADIAL-MFG 403.82,2543.91 r180 top value=47uF
C8 "GCJ32DC72A475KE01L" FP-GCJ32DC72A475KE01L_1210-MFG 1173.36,2374.7 r270 top value=4.7µF
C9 "C0603C102J5RACTU" 0603_HV 333,3100 r270 bottom value=1000pF
C10 "HMK107B7104KAHT" 0603_HV 1868.45,1109.45 r180 top value=0.1uF
C11 "HMK107B7104KAHT" 0603_HV 1868.45,1321.99 r180 top value=0.1uF
C12 "06033C104KAT2A" 0603_HV 1958.93,1304.66 r90 top value=0.1uF
C13 "CGA6N3X7R2A225K230AE" FP-CGA6N3X7R2A225K230AE_1210-MFG 1444.82,3223.42 r0 bottom
C14 "06031A330JAT2A" 0603_HV 2031.09,2090.58 r90 bottom value=33pF
C15 "06031A330JAT2A" 0603_HV 2361.12,2129.67 r90 bottom value=33pF
C16 "08051C105K4Z2A" 0805_150 1760.89,955.03 r270 top value=1uF
C17 "HMK107B7104KAHT" 0603L 2943.22,2146.28 r180 top value=0.1uF
C18 "06033C104KAT2A" 0603_HV 2371.89,1211.78 r180 top value=0.1uF
C19 "HMK107B7104KAHT" 0603_HV 1840.37,981.03 r270 top value=0.1uF
C20 "HMK107B7104KAHT" 0603_HV 1915.76,953.03 r270 top value=0.1uF
C21 "HMK107B7104KAHT" 0603_HV 2520.68,1216.07 r0 top value=0.1uF
C22 "CGA4J1X7R1E475K125AE" FP-CGA4J1X7R1E475K125AE_0805-MFG 2110.65,1364.21 r90 top value=4.7µF
C23 "HMK107B7104KAHT" 0603_HV 2548.68,994.76 r0 top value=0.1uF
C24 "HMK107B7104KAHT" 0603_HV 3185.59,2768 r270 bottom value=0.1uF
C25 "GCM1885C2A101JA16D" 0603_HV 2794.93,1085.69 r270 top value=100pF
C26 "CGA4J1X7R1E475K125AE" FP-CGA4J1X7R1E475K125AE_0805-MFG 2194.61,1362.47 r90 top value=4.7µF
C28 "GCJ32DC72A475KE01L" FP-GCJ32DC72A475KE01L_1210-MFG 2945.74,2323.27 r0 top value=4.7µF
C29 "C3225X7R2A106K250AC" FP-C3225X7R2A106K250AC_1210-MFG 3266.11,2389.53 r270 top value=10µF
C31 "CGA3E2X7R2A102K080AA" 0603 3081.1,2768 r270 bottom value=1000pF
C32 "HMK107B7104KAHT" 0603_HV 1983.89,953.03 r270 top value=0.1uF
C33 "12101C105KAT2A" FP-12101C105KAT2A_1210-MFG 87.51,137.9 r90 bottom value=1µF
C34 "C0603C474K4RACTU" 0603 1898.32,1211.54 r90 top value=0.47uF
C35 "C0603C474K4RACTU" 0603 2431.88,1091.03 r270 top value=0.47uF
C36 "C0603C102J5RACTU" 0603_HV 3027,1221 r315 bottom value=1000pF
C38 "80SXV47M" FP-100SXV22M_RADIAL-MFG 4027,2308 r0 top value=47uF
C39 "80SXV47M" FP-100SXV22M_RADIAL-MFG 3615,2749 r90 top value=47uF
C40 "GCJ32DC72A475KE01L" FP-GCJ32DC72A475KE01L_1210-MFG 3125.56,2389.53 r270 top value=4.7µF
C42 "C3225X7R2A106K250AC" FP-C3225X7R2A106K250AC_1210-MFG 1043,2374.29 r270 top value=10µF
C43 "CGA3E2C0G2A101J080AA" 0603 1388.68,2100 r0 top value=100pF
C44 "80SXV47M" FP-100SXV22M_RADIAL-MFG 383.73,2079.34 r180 top value=47uF
C45 "GCJ32DC72A475KE01L" FP-GCJ32DC72A475KE01L_1210-MFG 3106,2392.5 r270 bottom value=4.7µF
C46 "C3225X7R2A106K250AC" FP-C3225X7R2A106K250AC_1210-MFG 3251.73,2392.5 r270 bottom value=10µF
C48 "C0805C105K3RACTU" 0805_HV 705,350 r0 bottom value=1uF
C49 "12101C105KAT2A" FP-12101C105KAT2A_1210-MFG 218.68,139.07 r90 bottom value=1µF
C50 "C0603C221K5RACTU" 0603 573.69,322.88 r270 bottom value=220pF
C53 "C3225X7R2A106K250AC" FP-C3225X7R2A106K250AC_1210-MFG 2942,2257.82 r0 bottom value=10µF
C54 "GCJ32DC72A475KE01L" FP-GCJ32DC72A475KE01L_1210-MFG 2942,2123.5 r0 bottom value=4.7µF
C56 "C3225X7R2A106K250AC" FP-C3225X7R2A106K250AC_1210-MFG 3399,2402 r270 top value=10µF
C57 "80SXV47M" FP-100SXV22M_RADIAL-MFG 3539.82,2072.26 r180 top value=47uF
C60 "GCJ32DC72A475KE01L" FP-GCJ32DC72A475KE01L_1210-MFG 1173.21,2370.88 r90 bottom value=4.7µF
C63 "HMK107B7104KAHT" 0603L 698,1132.39 r270 bottom value=0.1uF
C70 "80SXV47M" FP-100SXV22M_RADIAL-MFG 882.81,1972.53 r0 top value=47uF
C74 "08051C105K4Z2A" 0805_150 1691.61,1072.49 r90 top value=1uF
C77 "08051C105K4Z2A" 0805_150 790.1,1132.39 r270 bottom value=1uF
C78 "08051C105K4Z2A" 0805_150 3279,2767 r270 bottom value=1uF
C80 "HMK107B7104KAHT" 0603L 1388.68,2162.53 r0 top value=0.1uF
C81 "08051C105K4Z2A" 0805_150 1388.68,2235 r0 top value=1uF
C82 "08051C105K4Z2A" 0805_150 2943.22,2214.91 r180 top value=1uF
C150 "C3225X7R2A106K250AC" FP-C3225X7R2A106K250AC_1210-MFG 873.79,2297.91 r0 top value=10µF
C151 "CGA3E2X7R2A102K080AA" 0603 608.58,1132.39 r270 bottom value=1000pF
C152 "CGA3E2C0G2A101J080AA" 0603 2943.22,2076.37 r180 top value=100pF
C200 "HMK107B7104KAHT" 0603_HV 1769.58,1079.68 r90 top value=0.1uF
C201 "C0603C104K8RACTU" 0603 2233.04,726.76 r180 top value=0.1uF
C202 "C0603C104K8RACTU" 0603 2513.26,727.97 r270 top value=0.1uF
C500 "T521X156M075ATE035" FP-T521X156M075ATE035_2917-MFG 392.82,2401.91 r180 top value=15µF
C501 "T521X156M075ATE035" FP-T521X156M075ATE035_2917-MFG 392,1933 r180 top value=15µF
C502 "T521X156M075ATE035" FP-T521X156M075ATE035_2917-MFG 874.47,2113.16 r0 top value=15µF
C503 "T521X156M075ATE035" FP-T521X156M075ATE035_2917-MFG 874.47,1868.99 r0 top value=15µF
C504 "T521X156M075ATE035" FP-T521X156M075ATE035_2917-MFG 3574.82,1933.91 r180 top value=15µF
C505 "T521X156M075ATE035" FP-T521X156M075ATE035_2917-MFG 3574.82,2214.91 r180 top value=15µF
C506 "T521X156M075ATE035" FP-T521X156M075ATE035_2917-MFG 3983,1974 r0 top value=15µF
C507 "T521X156M075ATE035" FP-T521X156M075ATE035_2917-MFG 3462,2713 r90 top value=15µF
C508 "T521X156M075ATE035" FP-T521X156M075ATE035_2917-MFG 402.98,2370.88 r180 bottom value=15µF
C509 "T521X156M075ATE035" FP-T521X156M075ATE035_2917-MFG 402.98,2146.89 r180 bottom value=15µF
C510 "T521X156M075ATE035" FP-T521X156M075ATE035_2917-MFG 402.98,1924.01 r180 bottom value=15µF
C511 "T521X156M075ATE035" FP-T521X156M075ATE035_2917-MFG 880.82,2147.87 r0 bottom value=15µF
C512 "T521X156M075ATE035" FP-T521X156M075ATE035_2917-MFG 576.2,2605.89 r135 bottom value=15µF
C513 "T521X156M075ATE035" FP-T521X156M075ATE035_2917-MFG 880.82,1925.2 r0 bottom value=15µF
C514 "T521X156M075ATE035" FP-T521X156M075ATE035_2917-MFG 3550,2008.25 r180 bottom value=15µF
C515 "T521X156M075ATE035" FP-T521X156M075ATE035_2917-MFG 3550,2227.52 r180 bottom value=15µF
C516 "T521X156M075ATE035" FP-T521X156M075ATE035_2917-MFG 3961.42,2648 r0 bottom value=15µF
C517 "T521X156M075ATE035" FP-T521X156M075ATE035_2917-MFG 3961.42,2438 r0 bottom value=15µF
C518 "T521X156M075ATE035" FP-T521X156M075ATE035_2917-MFG 3961.42,2222.91 r0 bottom value=15µF
C519 "T521X156M075ATE035" FP-T521X156M075ATE035_2917-MFG 3961.42,1976.79 r0 bottom value=15µF
D1 "SZBZX84C15LT3G" FP-SZBZX84C15LT3G_SOT23-MFG 448.49,3108.94 r270 bottom
D2 "V1FM10-M3/H" FP-V1FM10-M3-H_DO-219AB-MFG 2350.51,1442.17 r0 top
D3 "V1FM10-M3/H" FP-V1FM10-M3-H_DO-219AB-MFG 1964.28,1478.65 r0 top
D4 "150060VS75000" WL-SMCW_GREEN 3922.4,525.56 r0 top value=Green
D5 "150060VS75000" WL-SMCW_GREEN 3828,670.5 r270 top value=Green
D6 "150060VS75000" WL-SMCW_GREEN 3828,823 r270 top value=Green
D7 "FSV12100V" TO-277A 1663.62,1999.08 r180 bottom value=100V
D8 "FSV12100V" TO-277A 2974.89,1821 r270 bottom value=100V
D9 "VS-1EMH01HM3/5AT" FP-VS-1EMH01HM3_5AT_DO-214AC-MFG 412.97,517.5 r0 bottom
D10 "VS-1EMH01HM3/5AT" FP-VS-1EMH01HM3_5AT_DO-214AC-MFG 75,712.5 r90 bottom
FID1 "Fiducial" Fiducial10-20 3488.61,346.02 r0 top
FID2 "Fiducial" Fiducial10-20 362.48,83.87 r90 top
FID3 "Fiducial" Fiducial10-20 876.02,417.81 r90 top
FID4 "Fiducial" Fiducial10-20 362.48,83.87 r90 bottom
FID5 "Fiducial" Fiducial10-20 876.02,417.81 r90 bottom
FID6 "Fiducial" Fiducial10-20 3488.61,346.02 r90 bottom
H1 "SJ-5303 (CLEAR)" Bumpon_SJ5003Transparent 1811.44,3029.05 r180 bottom
H2 "SJ-5303 (CLEAR)" Bumpon_SJ5003Transparent 4148,3050 r180 bottom
H3 "SJ-5303 (CLEAR)" Bumpon_SJ5003Transparent 642.73,812.24 r180 bottom
H4 "SJ-5303 (CLEAR)" Bumpon_SJ5003Transparent 3227.17,564.24 r180 bottom
J1 "TB005-762-02BE" FP-TB005-762-02BE_TERM_CONN-MFG 1352.23,3029.05 r180 top
J2 "TB005-762-02BE" FP-TB005-762-02BE_TERM_CONN-MFG 279.14,1121.59 r270 top
J3 "TB005-762-02BE" FP-TB005-762-02BE_TERM_CONN-MFG 2938.23,3033.05 r180 top
J4 "N2510-6002-RB" CONN_2510-6002 4239,885.1 r270 top
J5 "0022053041" CONN_22-05-3041 4189,9 r0 top
J6 "0393570002" MOLEX_39357-0002 843,153 r0 top
J7 "109159005101916" FP-109159005101916_CONN_SSL_PLUG5-MFG 2122.91,3311.08 r0 top
J8 "TSW-104-07-G-D" TSW-104-07-G-D 3283,163 r0 top
JP1 "PEC02SAAN" CONN_PEC02SAAN 2767.87,932.59 r180 top
JP2 "PEC02SAAN" CONN_PEC02SAAN 2779.35,794.25 r180 top
JP3 "Header_2x1" CONN_PEC02SAAN 2187.34,594.5 r180 top
JP4 "Header_2x1" CONN_PEC02SAAN 2090.97,778.29 r270 top
JP5 "Header_2x1" CONN_PEC02SAAN 1799.03,519.15 r0 top
JP6 "Header_2x1" CONN_PEC02SAAN 2059.85,374.06 r0 top
JP7 "Header_2x1" CONN_PEC02SAAN 1813.1,383.15 r180 top
JP8 "Header_2x1" CONN_PEC02SAAN 1838.66,651.96 r180 top
JP9 "Header_2x1" CONN_PEC02SAAN 1818,792.25 r180 top
JP10 "Header_2x1" CONN_PEC02SAAN 2384.34,787.31 r270 top
JP11 "Header_2x1" CONN_PEC02SAAN 2429.24,599.34 r0 top
JP12 "PEC03SAAN" CONN_PEC03SAAN 1476,1475 r270 top
JP13 "PEC02SAAN" CONN_PEC02SAAN 3748,1223 r0 top
JP14 "PEC02SAAN" CONN_PEC02SAAN 3860,171 r270 top
JP15 "PEC02SAAN" CONN_PEC02SAAN 3724,525.56 r180 top
JP16 "Header_2x1" CONN_PEC02SAAN 145,522.5 r0 top
L1 "IHLP6767GZER100M01" FP-IHLP6767GZER100M01_SMT_INDUCTOR_17MM15_17MM15-MFG 2179.55,2176.98 r0 top value=10uH
L2 "CMLB135T-100MS" FP-CMLB135T-100MS_SMT2_13MM45_12Mm6-MFG 2150.02,1828.8 r0 top value=10uH
LBL1 "THT-14-423-10" Label_650x200 4054,3163 r0 top
LOGO1 "DANGER HIGH VOLTAGE" IEC_HighVoltage_Small 2850.75,132 r0 top
LOGO2 "CAUTION HOT SURFACE" IEC_HotSurface_Medium 4034,1604 r90 top
LOGO3 "CAUTION.  READ USER GUIDE BEFORE USE" IEC_Caution_Medium 2323.26,3029.05 r180 bottom
LOGO5 "CE Mark" CE_Mark_5mm 3250.1,679.21 r0 top
LOGO6 "FCC disclaimer" FCC_disclaimer 48,2215 r90 top
LOGO7 "WEEE logo" WEEE_Minimum 216.15,1709.77 r0 top
Q1 "SIR880BDP-T1-RE3" FP-SIR880BDP-T1-RE3_SO-8-MFG 1323.75,1856.14 r180 top
Q2 "SIR880BDP-T1-RE3" FP-SIR880BDP-T1-RE3_SO-8-MFG 1609.67,1889.99 r270 top
Q3 "SIR880BDP-T1-RE3" FP-SIR880BDP-T1-RE3_SO-8-MFG 3006.07,1825.8 r0 top
Q4 "SIR880BDP-T1-RE3" FP-SIR880BDP-T1-RE3_SO-8-MFG 2723.54,1967.26 r270 top
Q5 "AONS66917" FP-AONS66917_DFN8-MFG 675.79,3155.97 r270 top
Q6 "AONS66917" FP-AONS66917_DFN8-MFG 329,2964.54 r180 top
Q7 "AONS66917" FP-AONS66917_DFN8-MFG 3135.7,963.47 r180 top
Q8 "AONS66917" FP-AONS66917_DFN8-MFG 3187,1372.92 r0 top
R2 "WSL25125L000FEA" FP-WSL25125L000FEA_2512-MFG 610.82,1640.5 r0 top value=5m
R3 "CRCW06030000Z0EA" FP-CRCW06031R50FKEAHP_0603-MFG 2806.24,1703 r180 bottom value=0
R5 "CRCW060310R0FKEB" FP-CRCW060310R0FKEB_0603-MFG 1799.11,1176.27 r180 top value=10
R6 "CRCW060310R0FKEB" FP-CRCW060310R0FKEB_0603-MFG 1799.11,1247 r180 top value=10
R8 "CRCW06030000Z0EA" FP-CRCW06031R50FKEAHP_0603-MFG 1428.52,1946.44 r0 bottom value=0
R9 "CRCW06030000Z0EA" FP-CRCW06031R50FKEAHP_0603-MFG 2886.26,1201.2 r180 bottom value=0
R10 "CRCW120610R0FKEAHP" FP-CRCW120610R0FKEAHP_1206-MFG 1251.82,3225.42 r180 bottom value=10
R12 "CRCW06030000Z0EA" FP-CRCW06031R50FKEAHP_0603-MFG 597.22,2918 r90 bottom value=0
R13 "CRCW06030000Z0EA" FP-CRCW06031R50FKEAHP_0603-MFG 2028.2,1355.69 r90 top value=0
R14 "CRCW12103R30FKEAHP" 1210 1974,1949 r180 bottom value=3.30
R15 "CRCW12103R30FKEAHP" 1210 2465.59,2029.09 r270 bottom value=3.30
R17 "CRCW06030000Z0EA" FP-CRCW06031R50FKEAHP_0603-MFG 2619.97,2061.1 r0 bottom value=0
R20 "CRCW06030000Z0EA" FP-CRCW06031R50FKEAHP_0603-MFG 1449.97,2089.55 r0 bottom value=0
R21 "CRCW08051M00FKEAC" 0805_HV 1619.96,912.07 r0 top value=1.00Meg
R22 "CRCW060310R0FKEB" FP-CRCW060310R0FKEB_0603-MFG 2519.15,1147.83 r180 top value=10
R23 "CRCW06030000Z0EA" FP-CRCW06031R50FKEAHP_0603-MFG 2371.89,1305.62 r0 top value=0
R24 "FCSL110R005FER" FP-FCSL110R005FER_WIDE_4320-MFG 3549.04,1577.28 r180 top value=5m
R25 "CRCW060310R0FKEB" FP-CRCW060310R0FKEB_0603-MFG 2520.68,1069.88 r180 top value=10
R27 "ERJ-6ENF1333V" 0805_HV 1487.48,801.19 r90 top value=133k
R28 "ERJ-PB6B2493V" 0805_HV 2707.04,1098.12 r90 top value=249k
R30 "ERJ-6ENF2552V" 0805_HV 1619.96,790.63 r180 top value=25.5k
R32 "ERJ-6ENF3001V" 0805_HV 2522.5,1330 r180 top value=3.00k
R34 "RC0603FR-075K23L" 0603 1959.43,516.82 r270 top value=5.23k
R36 "CRCW0603133KFKEA" 0603 1982.27,801.19 r90 top value=133k
R41 "RC0603FR-0710KL" 0603 2105.73,483.1 r180 top value=10.0k
R45 "CRCW08050000Z0EA" FP-CRCW080510R0JNEAHP_0805-MFG 1515.37,1252.02 r180 top value=0
R46 "CRCW121020R0FKEAHP" FP-CRCW12104R30FKEAHP_1210-MFG 96.65,367.5 r270 bottom value=20
R48 "RC0603FR-07499KL" 0603 501.51,322.88 r90 bottom value=499k
R49 "CR0603-FX-3163ELF" FP-CR0603-FX-3163ELF_0603-MFG 472.11,190.18 r90 bottom value=316k
R50 "RC0603FR-072K21L" 0603 3906.05,429 r0 top value=2.21k
R51 "RC0603FR-072K21L" 0603 3924.56,685.1 r90 top value=2.21k
R52 "RC0603FR-072K21L" 0603 3924,832 r90 top value=2.21k
R53 "RC0603FR-0710KL" 0603 4149,371 r180 top value=10.0k
R54 "RC0603FR-0710KL" 0603 4318.71,371 r180 top value=10.0k
R55 "RC0603FR-0710KL" 0603 3886,340 r0 top value=10.0k
R56 "RC0603FR-0710KL" 0603 3899,948 r0 top value=10.0k
R59 "RC0805JR-070RL" 0805_HV 2780.2,1260.61 r90 top value=0
R64 "RG2012P-1372-B-T5" 0805_HV 2597.98,835.35 r90 top value=13.7k
R65 "RC0603FR-0730K1L" 0603 2024.57,598.23 r90 top value=30.1k
R66 "RC0603FR-072K49L" 0603 2331.76,949.96 r180 top value=2.49k
R67 "CRCW06034K99FKEAC" 0603 2201.54,833.94 r90 top value=4.99k
R68 "CRCW06030000Z0EA" FP-CRCW06031R50FKEAHP_0603-MFG 874.75,79.28 r135 bottom value=0
R69 "CRCW06030000Z0EA" FP-CRCW06031R50FKEAHP_0603-MFG 3774,50.37 r0 bottom value=0
R100 "CRCW06030000Z0EA" FP-CRCW06031R50FKEAHP_0603-MFG 1551.11,1079.92 r90 top value=0
R101 "CRCW06030000Z0EA" FP-CRCW06031R50FKEAHP_0603-MFG 1615.29,1016.24 r90 top value=0
R120 "CRCW08050000Z0EA" FP-CRCW080510R0JNEAHP_0805-MFG 1769.13,1460.93 r180 top value=0
R151 "RC1210JR-07100KL" 1210 914,2784 r90 bottom value=100k
R152 "RC1210JR-07100KL" 1210 995.67,944.62 r0 bottom value=100k
R153 "RC1210JR-07100KL" 1210 995.67,782.97 r0 bottom value=100k
R154 "RC1210JR-07100KL" 1210 902.53,1132.39 r90 bottom value=100k
R160 "CRCW06030000Z0EA" FP-CRCW06031R50FKEAHP_0603-MFG 1631.64,1557.58 r180 top value=0
R200 "RC0603JR-071K8L" 0603 2502.47,859.69 r90 top value=1.8k
R201 "RC0603JR-071K8L" 0603 2274.6,833.94 r90 top value=1.8k
R300 "CRCW08051R50FKEAHP" FP-CRCW080510R0JNEAHP_0805-MFG 1356.46,1422.55 r90 top value=1.5
R400 "RC1210JR-07100KL" 1210 3595.35,2763.97 r90 bottom value=100k
R401 "RC1210JR-07100KL" 1210 3427.43,2763.97 r90 bottom value=100k
R1000 "JR0805X35E" FP-JR0805X35E_0805-MFG 596.39,2957 r180 top value=0
R1001 "JR0805X35E" FP-JR0805X35E_0805-MFG 596.39,2876.5 r180 top value=0
R1002 "JR0805X35E" FP-JR0805X35E_0805-MFG 2942.71,1985.89 r0 top value=0
R1003 "JR0805X35E" FP-JR0805X35E_0805-MFG 2944.31,1972 r0 bottom value=0
R1004 "JR0805X35E" FP-JR0805X35E_0805-MFG 3395.91,1289.63 r270 top value=0
R1005 "JR0805X35E" FP-JR0805X35E_0805-MFG 3397,1291 r270 bottom value=0
SH-JP1 "SNT-100-BK-G" SNT-100-BK-G 1515,3590 r90 top value=1x2
SH-JP2 "SNT-100-BK-G" SNT-100-BK-G 1781,3577 r90 top value=1x2
SH-JP3 "SNT-100-BK-G" SNT-100-BK-G 1426.37,3917.26 r90 top value=1x2
SH-JP4 "SNT-100-BK-G" SNT-100-BK-G 1711.8,3917.26 r90 top value=1x2
SH-JP5 "SNT-100-BK-G" SNT-100-BK-G 2007.07,3917.26 r90 top value=1x2
SH-JP6 "SNT-100-BK-G" SNT-100-BK-G 2292.51,3917.26 r90 top value=1x2
SH-JP7 "SNT-100-BK-G" SNT-100-BK-G 2587.78,3917.26 r90 top value=1x2
SH-JP8 "SNT-100-BK-G" SNT-100-BK-G 2873.21,3917.26 r90 top value=1x2
SH-JP9 "SNT-100-BK-G" SNT-100-BK-G 3168.49,3917.26 r90 top value=1x2
SH-JP10 "SNT-100-BK-G" SNT-100-BK-G 3453.92,3917.26 r90 top value=1x2
SH-JP11 "SNT-100-BK-G" SNT-100-BK-G 3778.72,3917.26 r90 top value=1x2
TP1 "5002" Keystone5002 1631.64,367.5 r90 top
TP2 "5002" Keystone5002 1273.45,932.59 r90 top
TP3 "5002" Keystone5002 3475.28,3183.07 r90 top
TP4 "5002" Keystone5002 717.06,2793.63 r90 top
TP5 "5002" Keystone5002 2945.3,1285.99 r90 top
TP6 "5002" Keystone5002 3478.82,980.4 r90 top
TP7 "5002" Keystone5002 2502.47,463.57 r90 top
TP8 "5002" Keystone5002 2401.38,367.5 r90 top
TP9 "5002" Keystone5002 3699.5,948 r0 top
TP10 "5002" Keystone5002 1279.4,1296.53 r90 top
TP11 "5002" Keystone5002 1617.5,1387.5 r90 top
TP12 "5002" Keystone5002 1314.24,792.25 r90 top
TP13 "5002" Keystone5002 1428.34,635.59 r90 top
TP14 "5002" Keystone5002 1596.8,645.13 r90 top
TP15 "5002" Keystone5002 1221.64,1426.18 r90 top
TP16 "5002" Keystone5002 1617.5,506.86 r90 top
TP17 "5002" Keystone5002 2274.6,433.15 r90 top
TP18 "5002" Keystone5002 2051.01,2637 r90 top
TP19 "5002" Keystone5002 2257.14,2637 r90 top
TP20 "5002" Keystone5002 2698.25,1572.84 r90 top
TP21 "5002" Keystone5002 3733,1088 r180 top
TP22 "5002" Keystone5002 2612.07,1452.92 r90 top
TP23 "5002" Keystone5002 2758.79,1452.92 r90 top
TP24 "5002" Keystone5002 2790.6,645.13 r90 top
TP25 "5002" Keystone5002 1331.21,1597.65 r90 top
TP26 "5002" Keystone5002 1349.61,1064.95 r90 top
TP27 "5002" Keystone5002 2900.2,1418.18 r90 top
TP28 "5002" Keystone5002 2515.4,1546.68 r90 top
TP29 "5002" Keystone5002 3699.5,664.6 r0 top
TP30 "5002" Keystone5002 3675,132 r180 top
TP31 "5002" Keystone5002 3698,800.5 r0 top
TP32 "5002" Keystone5002 576,89 r90 top
TP33 "5002" Keystone5002 3938.26,1085.1 r90 top
TP34 "5002" Keystone5002 3940,1237 r90 top
TP35 "5016" Testpoint_Keystone_Compact 1460.8,417.75 r90 top
TP36 "5016" Testpoint_Keystone_Compact 148,344 r0 top
TP37 "5016" Testpoint_Keystone_Compact 2387,2992 r0 top
TP38 "5016" Testpoint_Keystone_Compact 3666.9,318.08 r90 top
TP39 "5016" Testpoint_Keystone_Compact 2752,433.15 r0 top
TP40 "5016" Testpoint_Keystone_Compact 1938,2992 r180 top
TP41 "5002" Keystone5002 2872.64,1593.12 r90 top
TP42 "5002" Keystone5002 2616.61,644.7 r0 top
TP43 "5002" Keystone5002 1818,2605.19 r90 top
TP44 "5002" Keystone5002 2499.14,2605.19 r90 top
TP45 "5002" Keystone5002 119,2956 r90 top
TP46 "5002" Keystone5002 653,1390.18 r90 top
TP47 "5016" Testpoint_Keystone_Compact 153.66,131 r0 top
U1 "BQ25750RRVT" RRV0036A-MFG 2150.02,1115.24 r90 top locked
U2 "LT3010EMS8E#PBF" FP-LT3010EMS8E-PBF_MSOP8-MFG 327.62,303.79 r180 bottom
ZZ1 "These assemblies are ESD sensitive, ESD precautions shall be observed." AssemblyNote 536,4863 r0 top
ZZ2 "These assemblies must be clean and free from flux and all contaminants. Use of no clean flux is not acceptable." AssemblyNote 532,4727 r0 top
ZZ3 "These assemblies must comply with workmanship standards IPC-A-610 Class 2, unless otherwise specified." AssemblyNote 526,4590 r0 top
ZZ4 "Install label in silkscreened box after final wash.  Text shall be 8 pt font.  Text shall be per the Label Table in the PDF schematic." AssemblyNote 524,4464 r0 top
ZZ5 "For BQ25750 variant, Install JP1, JP4, JP5, JP6, JP9, JP10, pin 1-2 of JP12, JP13, JP14, JP15, and JP16" AssemblyNote 524,4346 r0 top
ZZ6 "For BQ25758 variant, Install JP4, JP5, JP6, JP9, JP10, pin 1-2 of JP12, JP13, JP14, JP15, and JP16" AssemblyNote 521,4223 r0 top
ZZ7 "For BQ25756 variant, Install JP1, JP4, JP5, JP6, JP9, JP10, pin 1-2 of JP12, JP13, JP14, JP15, and JP16" AssemblyNote 518,4119 r0 top

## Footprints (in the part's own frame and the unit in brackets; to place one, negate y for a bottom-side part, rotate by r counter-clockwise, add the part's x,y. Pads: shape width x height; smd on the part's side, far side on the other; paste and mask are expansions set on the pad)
0603 [mm] "0603 from SM-752 data"
  rect 1x0.95 smd: 1(-0.8,0) 2(0.8,0)
  silkscreen extent -1.52,-0.69 1.52,0.69, body extent -0.87,-0.47 0.87,0.47, height 1
0603_HV [mil] "Ernesto recommended land pattern.  26 mil between pads."
  rect 30x30 smd: 1(-28,0) 2(28,0)
  silkscreen extent -52,-24 52,24, body extent -34,-19 34,19, height 39
0603L [mm] "0603 from SM-752 data"
  rect 0.8x0.85 smd: 1(-0.7,0) 2(0.7,0)
  silkscreen extent -0.07,-0.33 0.07,0.33, body extent -0.87,-0.47 0.87,0.47, height 1
0805_150 [mm] "0805 / 1.5 mm height"
  rect 1.15x1.45 smd: 1(-0.9,0) 2(0.9,0)
  silkscreen extent -0.1,-0.8 0.1,0.8, body extent -1.1,-0.72 1.1,0.72, height 1.5
0805_HV [mil] "0805 with 30mil clearance between pads"
  rect 50x63 smd: 1(-40,0) 2(40,0)
  silkscreen extent -74,-40 74,40, body extent -43,-29 43,29, height 57
1210 [mm] "1210 from SM-752 data"
  rect 1.3x2.7 smd: 1(-1.45,0) 2(1.45,0)
  silkscreen extent -2.32,-1.57 2.32,1.57, body extent -1.7,-1.35 1.7,1.35, height 1.35
AssemblyNote [mil] "Assembly Note"
Bumpon_SJ5003Transparent [mil] "3M Hemispherical Bumpon transparent"
  round 1 on Mech4: 0(0,0)
  silkscreen extent -228,-228 228,228, body extent -219,-219 219,219, height 197
CE_Mark_5mm [mil] "Minimum text height for CE Mark"
  silkscreen extent -138,-98 138,98
CONN_22-05-3041 [mm] "MOLEX"
  rect 1.65x1.65 hole 1.02: 1(-3.81,5.7)
  round 1.65 hole 1.02: 2(-1.27,5.7) 3(1.27,5.7) 4(3.81,5.7)
  silkscreen extent -5,0 5,4.18, body extent -5,-6.91 5,6.02, height 6.37
CONN_2510-6002 [mm] "3M 2500 series TS-0770-L December 15, 2011"
  rect 1.65x1.65 hole 1.016 mask+0: 1(-5.08,-1.27)
  round 1.65 hole 1.016 mask+0: 2(-5.08,1.27) 3(-2.54,-1.27) 4(-2.54,1.27) 5(0,-1.27) 6(0,1.27) 7(2.54,-1.27) 8(2.54,1.27) 9(5.08,-1.27) 10(5.08,1.27)
  silkscreen extent -10.01,-4.17 10.01,4.47, body extent -10.01,-4.11 10.01,4.52, height 9.92
CONN_PEC02SAAN [mm] "SULLINS"
  rrect7% 1.5x1.5 hole 1.016: 1(-1.27,0)
  round 1.5 hole 1.016: 2(1.27,0)
  silkscreen extent -2.54,-1.52 2.54,1.27, body extent -2.54,-1.27 2.54,1.27, height 8.38
CONN_PEC03SAAN [mm] "SULLINS"
  rect 1.5x1.5 hole 1.016: 1(-2.54,0)
  round 1.5 hole 1.016: 2(0,0) 3(2.54,0)
  silkscreen extent -4.72,-1.27 3.81,1.27, body extent -3.84,-1.3 3.84,1.3, height 8.38
FCC_disclaimer [mil]
Fiducial10-20 [mm]
  round 1 smd mask+0.5: 1(0,0)
  Top Layer keep-out circle w1.178: c0,0 r0.5
FP-100SXV22M_RADIAL-MFG [mm]
  rrect5% 4.4x1.9 smd paste+0 mask+0: 1(-4.35,0) 2(4.35,0)
  silkscreen extent -7.23,-5.25 5.25,5.25, body extent -6.8,-5.5 6.8,5.5, height 0.25
FP-12101C105KAT2A_1210-MFG [mm]
  rrect10% 1x2.5 smd paste+0 mask+0: 1(-1.5,0) 2(1.5,0)
  silkscreen extent -0.62,-1.4 0.62,1.4, body extent -1.65,-1.25 1.65,1.25, height 2.79
FP-109159005101916_CONN_SSL_PLUG5-MFG [mm]
  rrect8% 1.2x2 smd paste+0 mask+0: 1(6,-2.3) 2(3,-2.3) 3(0,-2.3) 4(-3,-2.3) 5(-6,-2.3)
  rrect7% 1.5x1.6 smd paste+0 mask+0: 6(-8.435,-1.35) 7(8.435,-1.35)
  silkscreen extent -8.5,-3.97 8.5,-2.52, body extent -9.29,-3.4 9.29,2.7, height 0.25
FP-AONS66917_DFN8-MFG [mm]
  rrect20% 0.5x0.65 smd paste+0 mask+0: 1(-1.905,-2.755) 2(-0.635,-2.755) 3(0.635,-2.755) 4(1.905,-2.755)
  round 3.687 smd paste+0 mask+0: 5-6-7-8(-0.036,0.448)
  Top Layer region: -2.3,-1.6 2.3,-1.6 2.3,2.52 2.155,2.52 2.155,3.07 1.655,3.07 1.655,2.52 0.885,2.52 0.885,3.07 0.385,3.07 0.385,2.52 -0.385,2.52 -0.385,3.07 -0.885,3.07 -0.885,2.52 -1.655,2.52 -1.655,3.07 -2.155,3.07 -2.155,2.52 -2.3,2.52
  silkscreen extent -3,-3.77 3,2.6, body extent -2.9,-3.18 2.9,3.17, height 0.25
FP-C3225X7R2A106K250AC_1210-MFG [mm]
  rrect9% 1.1x2.2 smd paste+0 mask+0: 1(-1.65,0) 2(1.65,0)
  silkscreen extent -0.72,-1.43 0.72,1.43, body extent -1.6,-1.25 1.6,1.25, height 2.85
FP-CGA4J1X7R1E475K125AE_0805-MFG [mm]
  rrect13% 0.8x1.05 smd paste+0 mask+0: 1(-0.925,0) 2(0.925,0)
  silkscreen extent -0.15,-0.72 0.15,0.72, body extent -1.43,-0.82 1.43,0.82, height 0.25
FP-CGA6N3X7R2A225K230AE_1210-MFG [mm]
  rrect9% 1.1x2.2 smd paste+0 mask+0: 1(-1.65,0) 2(1.65,0)
  body extent -1.6,-1.25 1.6,1.25, height 2.3
FP-CMLB135T-100MS_SMT2_13MM45_12Mm6-MFG [mm]
  rrect3% 3.25x5 smd paste+0 mask+0: 1(-5.625,0) 2(5.625,0)
  silkscreen extent -6.9,-6.4 6.9,6.4, body extent -7.35,-6.5 7.35,6.5, height 0.25
FP-CR0603-FX-3163ELF_0603-MFG [mm]
  rrect15% 0.65x0.9 smd paste+0 mask+0: 1(-0.725,0) 2(0.725,0)
  silkscreen extent 0,-0.45 0,0.45, body extent -0.8,-0.4 0.8,0.4, height 0.55
FP-CRCW06031R50FKEAHP_0603-MFG [mm]
  rrect13% 0.75x1 smd paste+0 mask+0: 1(-0.75,0) 2(0.75,0)
  silkscreen extent -0.8,-0.9 0.8,0.9, body extent -0.8,-0.43 0.8,0.43, height 0.55
FP-CRCW12104R30FKEAHP_1210-MFG [mm]
  rrect9% 1.1x2.8 smd paste+0 mask+0: 1(-1.4,0) 2(1.4,0)
  silkscreen extent -0.48,-1.35 0.48,1.35, body extent -1.6,-1.25 1.6,1.25, height 0.7
FP-CRCW060310R0FKEB_0603-MFG [mm]
  rrect13% 0.75x1 smd paste+0 mask+0: 1(-0.75,0) 2(0.75,0)
  silkscreen extent -0.8,-0.9 0.8,0.9, body extent -1.22,-0.6 1.22,0.6, height 0.25
FP-CRCW080510R0JNEAHP_0805-MFG [mm]
  rrect11% 0.95x1.45 smd paste+0 mask+0: 1(-0.975,0) 2(0.975,0)
  silkscreen extent -0.13,-0.7 0.13,0.7, body extent -1.55,-0.82 1.55,0.82, height 0.25
FP-CRCW120610R0FKEAHP_1206-MFG [mm]
  rrect10% 1.05x1.8 smd paste+0 mask+0: 1(-1.275,0) 2(1.275,0)
  silkscreen extent -0.38,-0.87 0.38,0.87, body extent -1.55,-0.8 1.55,0.8, height 0.65
FP-FCSL110R005FER_WIDE_4320-MFG [mm]
  rrect10% 1x11.2 smd paste+0 mask+0: 1(-2.3,0) 2(2.3,0)
  silkscreen extent -1.43,-5.6 1.43,5.6, body extent -2.5,-5.5 2.5,5.5, height 0.7
FP-GCJ32DC72A475KE01L_1210-MFG [mm]
  rrect9% 1.1x2.05 smd paste+0 mask+0: 1(-1.65,0) 2(1.65,0)
  silkscreen extent -1.8,-1.4 1.8,1.4, body extent -1.6,-1.25 1.6,1.25, height 2.3
FP-IHLP6767GZER100M01_SMT_INDUCTOR_17MM15_17MM15-MFG [mm]
  rrect3% 3.825x12.32 smd paste+0 mask+0: 1(-8.117,0) 2(8.117,0)
  silkscreen extent -8.64,-8.57 8.64,8.57, body extent -10.13,-8.67 10.13,8.67, height 0.25
FP-JR0805X35E_0805-MFG [mm]
  rrect7% 1.4x1.44 smd paste+0 mask+0: 1(-1.1,0) 2(1.1,0)
  silkscreen extent 0,-0.72 0,0.72, body extent -1.9,-0.82 1.9,0.82, height 0.25
FP-LT3010EMS8E-PBF_MSOP8-MFG [mm]
  rrect24% 0.889x0.42 smd paste+0 mask+0: 1(-2.105,0.975) 2(-2.105,0.325) 3(-2.105,-0.325) 4(-2.105,-0.975) 5(2.105,-0.975) 6(2.105,-0.325) 7(2.105,0.325) 8(2.105,0.975)
  rrect6% 1.68x1.88 smd paste+0 mask+0: 9(0,0)
  silkscreen extent -3.27,-1.55 1.55,1.55, body extent -2.47,-1.5 2.47,1.5, height 1.1
FP-SIR880BDP-T1-RE3_SO-8-MFG [mil]
  rrect16% 50x24 smd paste+0 mask+0: 1(-105,75) 2(-105,25) 3(-105,-25) 4(-105,-75)
  round 132.13 smd paste+0 mask+0: 5-6-7-8(25.41,2.72)
  Top Layer region: -48,77 90,77 90,87 130,87 130,63 102,63 102,37 130,37 130,13 102,13 102,-13 130,-13 130,-37 102,-37 102,-63 130,-63 130,-87 90,-87 90,-77 -48,-77
  silkscreen extent -157,-110 118,110, body extent -134,-107 134,107, height 10
FP-SZBZX84C15LT3G_SOT23-MFG [mm]
  rrect13% 0.9x0.8 smd paste+0 mask+0: 1(-1,0.95) 2(-1,-0.95) 3(1,0)
  silkscreen extent -0.7,-1.52 0.7,1.52, body extent -1.2,-1.45 1.2,1.45, height 1.11
FP-T521X156M075ATE035_2917-MFG [mm]
  rrect5% 1.99x2.33 smd paste+0 mask+0: 1(-3.01,0) 2(3.01,0)
  silkscreen extent -3.8,-2.3 4.9,2.3, body extent -4.13,-2.42 4.13,2.42, height 0.25
FP-TB005-762-02BE_TERM_CONN-MFG [mm]
  rrect4% 2.45x2.45 hole 1.6 paste-1000 mask+0: 1(-3.51,1.6)
  round 2.45 hole 1.6 paste-1000 mask+0: 2(4.11,1.6)
  silkscreen extent -8.83,-6.5 8.25,6.5, body extent -8.34,-6.6 8.34,6.6, height 0.25
FP-V1FM10-M3-H_DO-219AB-MFG [mm]
  rrect8% 1.3x1.4 smd paste+0 mask+0: 1(1.45,0) 2(-1.45,0)
  silkscreen extent -0.43,-0.95 2.79,0.95, body extent -2.2,-1.05 2.2,1.05, height 0.25
FP-VS-1EMH01HM3_5AT_DO-214AC-MFG [mm]
  rrect6% 1.7x1.68 smd paste+0 mask+0: 1(-1.79,0) 2(1.79,0)
  silkscreen extent -3.37,-1.4 2.25,1.4, body extent -2.55,-1.33 2.55,1.33, height 2.29
FP-WSL25125L000FEA_2512-MFG [mm]
  rrect5% 2.11x3.68 smd paste+0 mask+0: 1(-2.645,0) 2(2.645,0)
  silkscreen extent -1.21,-1.72 1.21,1.72, body extent -3.8,-1.94 3.8,1.94, height 0.25
IEC_Caution_Medium [mil]
  silkscreen extent -217,-183 217,193
IEC_HighVoltage_Small [mil]
  silkscreen extent -107,-88 107,97
IEC_HotSurface_Medium [mil]
  silkscreen extent -217,-188 217,188
Keystone5002 [mil] "For Keystone 500x miniature loop terminals"
  round 80 hole 40: 1(0,0)
  silkscreen extent -52,-52 52,52, body extent -49,-49 49,49, height 182
Label_650x200 [mil] "Thermal Transfer Label"
  round 1 on Mech13: 0(0,0)
  silkscreen extent -325,-100 325,100, body extent -325,-100 325,100, height 1
MOLEX_39357-0002 [mm] "Terminal Block, 3.5 mm, 2x1, TH"
  rect 1.6x1.6 hole 1.1: 1(-1.75,0)
  round 1.6 hole 1.1: 2(1.75,0)
  silkscreen extent -3.86,-3.45 3.5,3.84, body extent -3.55,-3.45 3.56,3.84, height 8.51
RRV0036A-MFG [mm]
  rrect40% 0.6x0.25 smd paste+0 mask+0: 1(-2.4,2.25) 2(-2.4,1.75) 3(-2.4,1.25) 4(-2.4,0.75) 5(-2.4,0.25) 6(-2.4,-0.25) 7(-2.4,-0.75) 8(-2.4,-1.25) 9(-2.4,-1.75) 10(-2.4,-2.25) 19(2.4,-2.25) 20(2.4,-1.75) 21(2.4,-1.25) 22(2.4,-0.75) 23(2.4,-0.25) 24(2.4,0.25) 25(2.4,0.75) 26(2.4,1.25) 27(2.4,1.75) 28(2.4,2.25)
  rrect40% 0.25x0.6 smd paste+0 mask+0: 11(-1.75,-2.9) 12(-1.25,-2.9) 13(-0.75,-2.9) 14(-0.25,-2.9) 15(0.25,-2.9) 16(0.75,-2.9) 17(1.25,-2.9) 18(1.75,-2.9) 29(1.75,2.9) 30(1.25,2.9) 31(0.75,2.9) 32(0.25,2.9) 33(-0.25,2.9) 34(-0.75,2.9) 35(-1.25,2.9) 36(-1.75,2.9)
  rrect3% 3.6x4.6 smd paste-1000 mask+0: 37(0,0)
  silkscreen extent -3.4,-3.05 2.55,3.05, body extent -2.8,-3.3 2.8,3.3, height 0.25
SNT-100-BK-G [mil] "Samtec STEP model"
  round 1 on Mech3: 0(0,0)
  body extent -100,-50 100,50, height 344
Testpoint_Keystone_Compact [mil] "Compact SMT test point"
  rect 185x135 smd: 1(0,0)
  silkscreen extent -110,-80 110,80, body extent -75,-56 75,56, height 91
TO-277A [mm] "Vishay"
  rect 1.4x1.27 smd: 1(-1.04,1.83) 2(1.04,1.83)
  rect 4.72x4.8 smd: 3(0,-1.883)
  silkscreen extent -2.7,1.45 -2.4,1.75, body extent -2.35,-4.2 2.4,2.45, height 1.2
TSW-104-07-G-D [mm] "Samtec 100mil, 2x4, 230 mil above insulator"
  rrect6% 1.65x1.65 hole 1.016: 1(-3.81,-1.27)
  round 1.65 hole 1.016: 2(-3.81,1.27) 3(-1.27,-1.27) 4(-1.27,1.27) 5(1.27,-1.27) 6(1.27,1.27) 7(3.81,-1.27) 8(3.81,1.27)
  silkscreen extent -6.1,-2.54 5.08,2.54, body extent -5.08,-2.54 5.08,2.54, height 8.38
WEEE_Minimum [mil] "WEEElie bin"
  silkscreen extent -95,-172 99,104
WL-SMCW_GREEN [mm] "WURTH"
  rect 0.8x0.8 smd: 1(-0.8,0) 2(0.8,0)
  silkscreen extent -1.9,-0.8 1.2,0.8, body extent -0.85,-0.45 0.85,0.45, height 0.8

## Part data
C2 C3 C5 C8 C28 C40 C45 C54 C60: library part CMP-0093675-1, "4.7uF ±10% 100V Ceramic Capacitor X7S 1210 (3225 Metric)", Manufacturer=Murata, Operating Temperature Range="-55°C to +125°C", TempCo=22%, Temperature Characteristic=X7S, Tolerance_%=10%, ValueDisplayed=4.7uF
C4 C6 C29 C42 C46 C53 C56 C150: library part CMP-0096021-1, "10 µF ±10% 100V Ceramic Capacitor X7R 1210 (3225 Metric)", Digikey Part Number=445-C3225X7R2A106K250ACCT-ND, Manufacturer=TDK, Mouser Part Number=810-C3225X7R2A106K25, Operating Temperature Range="-55°C to +125°C", TempCo=15%, Temperature Characteristic=X7R, Tolerance_%=10%, ValueDisplayed=10uF
C7 C38 C39 C44 C57 C70: library part CMP-0095409-1, "Aluminum Organic Polymer Capacitors 80VDC 47uF 20% SMD 980mA Halogen Free", Digikey Part Number=P122446CT-ND, Leakage Current=110uA, Manufacturer=Panasonic, Mouser Part Number=667-100SXV22M, Operating Temperature Range="-55°C to +125°C", Tolerance_%=20%, ValueDisplayed=47uF
C9 C36: library part CMP-0006845-4, "CAP, CERM, 1000 pF, 50 V, +/- 5%, X7R, 0603", Cap_Case=0603, Manufacturer=Kemet, Supplier Part Number 1=399-1083-1-ND, TempCo=X7R, Tolerance_%=5%, Value1=Unknown, Value2=50V, ValueDisplayed=1000pF
C10 C11 C17 C19 C20 C21 C23 C24 C32 C63 C80 C200: library part CMP-0081011-1, "CAP, CERM, 0.1 µF, 100 V,+/- 10%, X7R, AEC-Q200 Grade 1, 0603", Cap_Case=0603, Manufacturer="Taiyo Yuden", Supplier Part Number 1=587-6009-1-ND, TempCo=X7R, Tolerance_%=10%, Value2=100V, ValueDisplayed=0.1µF
C12 C18: library part CMP-0006753-4, "CAP, CERM, 0.1 uF, 25 V, +/- 10%, X7R, 0603", Cap_Case=0603, Manufacturer=AVX, Supplier Part Number 1=478-3714-1-ND, TempCo=X7R, Tolerance_%=10%, Value1="0.05 ohm", Value2=25V, ValueDisplayed=0.1uF
C13: library part CMP-0087124-1, "Cap Ceramic 2.2uF 100V X7R 10% SMD 1210 FlexiTerm 125C Plastic T/R", Manufacturer="TDK Corporation", TempCo=15%, Tolerance_%=10%
C14 C15: library part CMP-0006722-4, "CAP, CERM, 33 pF, 100 V, +/- 5%, C0G/NP0, 0603", Cap_Case=0603, Manufacturer=AVX, Supplier Part Number 1=478-1143-1-ND, TempCo=C0G/NP0, Tolerance_%=5%, Value1="0.209 ohm", Value2=100V, ValueDisplayed=33pF
C16 C74 C77 C78 C81 C82: library part CMP-0861070-1, "CAP, CERM, 1 µF, 100 V,+/- 10%, X7R, AEC-Q200 Grade 1, 0805", Cap_Case=0805, Manufacturer=AVX, TempCo=X7R, Tolerance_%=10%, Value2=100V, ValueDisplayed=1µF
C22 C26: library part CMP-0093626-1, "Cap Ceramic 4.7uF 25V X7R 10% Pad SMD 0805 +125°C Automotive T/R", Manufacturer="TDK Corporation", Operating Temperature Range="-55°C to +125°C", TempCo=15%, Temperature Characteristic=X7R, Tolerance_%=0.1%, ValueDisplayed=4.7uF
C25: library part CMP-0007130-4, "CAP, CERM, 100 pF, 100 V, +/- 5%, C0G/NP0, AEC-Q200 Grade 1, 0603", Cap_Case=0603, Manufacturer=MuRata, Supplier Part Number 1=490-4771-1-ND, TempCo=C0G/NP0, Tolerance_%=5%, Value1=Unknown, Value2=100V, ValueDisplayed=100pF
C31 C151: library part CMP-0007081-4, "Multilayer Ceramic Capacitors MLCC - SMD/SMT CGA 0603 100V 1000pF X7R 10% AEC-Q200", Cap_Case=0603, Manufacturer=TDK, Supplier Part Number 1=445-5806-1-ND, TempCo=X7R, Tolerance_%=10%, Value1="1.97137 ohm", Value2=100V, ValueDisplayed=1000pF
C33 C49: library part CMP-0093624-1, "General Purpose Ceramic Capacitor, 1210, 1uF, 10%, X7R, 15%, 100V", Manufacturer=AVX, Operating Temperature Range="-55°C to +125°C", TempCo=15%, Temperature Characteristic=X7R, Tolerance_%=10%, ValueDisplayed=1uF
C34 C35: library part CMP-0006944-4, "CAP, CERM, 0.47 uF, 16 V, +/- 10%, X7R, 0603", Cap_Case=0603, Manufacturer=Kemet, Supplier Part Number 1=399-4922-1-ND, TempCo=X7R, Tolerance_%=10%, Value1=Unknown, Value2=16V, ValueDisplayed=0.47uF
C43 C152: library part CMP-0007237-3, "Multilayer Ceramic Capacitors MLCC - SMD/SMT CGA 0603 100V 100pF C0G 5% AEC-Q200", Cap_Case=0603, Manufacturer=TDK, Supplier Part Number 1=490-1351-1-ND, TempCo=C0G/NP0, Tolerance_%=5%, Value1=Unknown, Value2=100V, ValueDisplayed=100pF
C48: library part CMP-0007728-2, "CAP, CERM, 1 uF, 25 V, +/- 10%, X7R, 0805", Cap_Case=0805, Manufacturer=Kemet, Supplier Part Number 1=399-8004-1-ND, TempCo=X7R, Tolerance_%=10%, Value1=Unknown, Value2=25V, ValueDisplayed=1uF
C50: library part CMP-0006895-4, "CAP, CERM, 220 pF, 50 V, +/- 10%, X7R, 0603", Cap_Case=0603, Manufacturer=Kemet, Supplier Part Number 1=399-1071-1-ND, TempCo=X7R, Tolerance_%=10%, Value1=Unknown, Value2=50V, ValueDisplayed=220pF
C201 C202: library part CMP-0006862-5, "CAP, CERM, 0.1 uF, 10 V, +/- 10%, X7R, 0603", Cap_Case=0603, Manufacturer=Kemet, Supplier Part Number 1=399-1095-1-ND, TempCo=X7R, Tolerance_%=10%, Value1=Unknown, Value2=10V, ValueDisplayed=0.1uF
C500 C501 C502 C503 C504 C505 C506 C507 C508 C509 C510 C511 C512 C513 C514 C515 C516 C517 C518 C519: library part CMP-0096796-1, "Cap Tant Polymer 15uF 75VDC X CASE 20% (7.3 X 4.3 X 4mm) SMD 7343-43 0.035 Ohm 125C T/R", Digikey Part Number=399-13123-1-ND, Leakage Current=112.5uA, Manufacturer=KEMET, Mouser Part Number=80-T521X156M75ATE35, Operating Temperature Range="-55°C to +125°C", Tolerance_%=20%, ValueDisplayed=15uF
D1: library part CMP-0093134-1, "Zener Diode Single 15V 5% 30Ohm 300mW Automotive 3-Pin SOT-23 T/R", Digikey Part Number=SZBZX84C15LT3GOSCT-ND, Manufacturer="On Semiconductor", Max Reverse Leakage Current=0.05uA, Mouser Part Number=863-SZBZX84C15LT3G, Operating Temperature Range="-65°C to +150°C", Power_W=250mW
D2 D3: library part CMP-0093639-2, "Diode Schottky 1A Surface Mount DO-219AB (SMF)", Digikey Part Number=112-V1FM10-M3/HCT-ND, Forward Current=1A, Manufacturer=Vishay, Max Surge Forward Current=30A, Mouser Part Number=78-V1FM10-M3/H, Operating Temperature Range="-40°C to +175°C", Peak Reverse Current=0.2uA, ValueDisplayed=95pF
D4 D5 D6: library part CMP-0002894-2, "LED, Green, SMD", Color=green, Manufacturer="Wurth Elektronik", Value1=W, Value2=2V
D7 D8: library part CMP-0028821-2, "Diode, Schottky, 100 V, 12 A, AEC-Q101, TO-277A", Manufacturer="Fairchild Semiconductor", Value1=12A, Value2=0.67V
D9 D10: library part CMP-0096827-2, "Diode Standard 100 V 1A Surface Mount DO-214AC (SMA)", Digikey Part Number=VS-1EMH01HM3/5AT-ND, Forward Current=1A, Manufacturer=Vishay, Max Surge Forward Current=50A, Mouser Part Number=78-VS-1EMH01HM35AT, Operating Temperature Range="-55°C to +175°C", Peak Reverse Current=2uA, ValueDisplayed=8.5pF
FID1 FID2 FID3 FID4 FID5 FID6: library part CMP-0077181-1, "Fiducial mark.  There is nothing to buy or mount.", Manufacturer=N/A
H1 H2 H3 H4: library part CMP-0003620-1, "Bumpon, Hemisphere, 0.44 X 0.20, Clear", Manufacturer=3M, Supplier Part Number 1=SJ5303-7-ND
J1 J2 J3: library part CMP-0093294-2, Current_A=30A, Digikey Part Number=102-6189-ND, Manufacturer="CUI Devices", Mouser Part Number=490-TB005-762-02BE, Operating Temperature Range="-40°C to +105°C", Voltage_V=300V
J4: library part CMP-0055448-2, "Header (shrouded), 100mil, 5x2, High-Temperature, Gold, TH", Manufacturer=3M, Supplier Part Number 1=MHC10K-ND
J5: library part CMP-0055187-1, "Header (friction lock), 100mil, 4x1, R/A, TH", Manufacturer=Molex, Supplier Part Number 1=WM4302-ND
J6: library part CMP-0055341-2, "Terminal Block, 3.5 mm, 2x1, Tin, TH", Manufacturer=Molex, Supplier Part Number 1=WM7877-ND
